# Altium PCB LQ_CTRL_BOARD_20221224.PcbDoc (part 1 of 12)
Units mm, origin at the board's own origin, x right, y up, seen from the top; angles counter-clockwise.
Board outline 260 x 142 mm, 6 copper layers (Top Layer, Mid-Layer 1, Mid-Layer 2, Mid-Layer 3, Mid-Layer 4, Bottom Layer); 1105 components, 1039 nets, 3898 pads, 1277 vias.
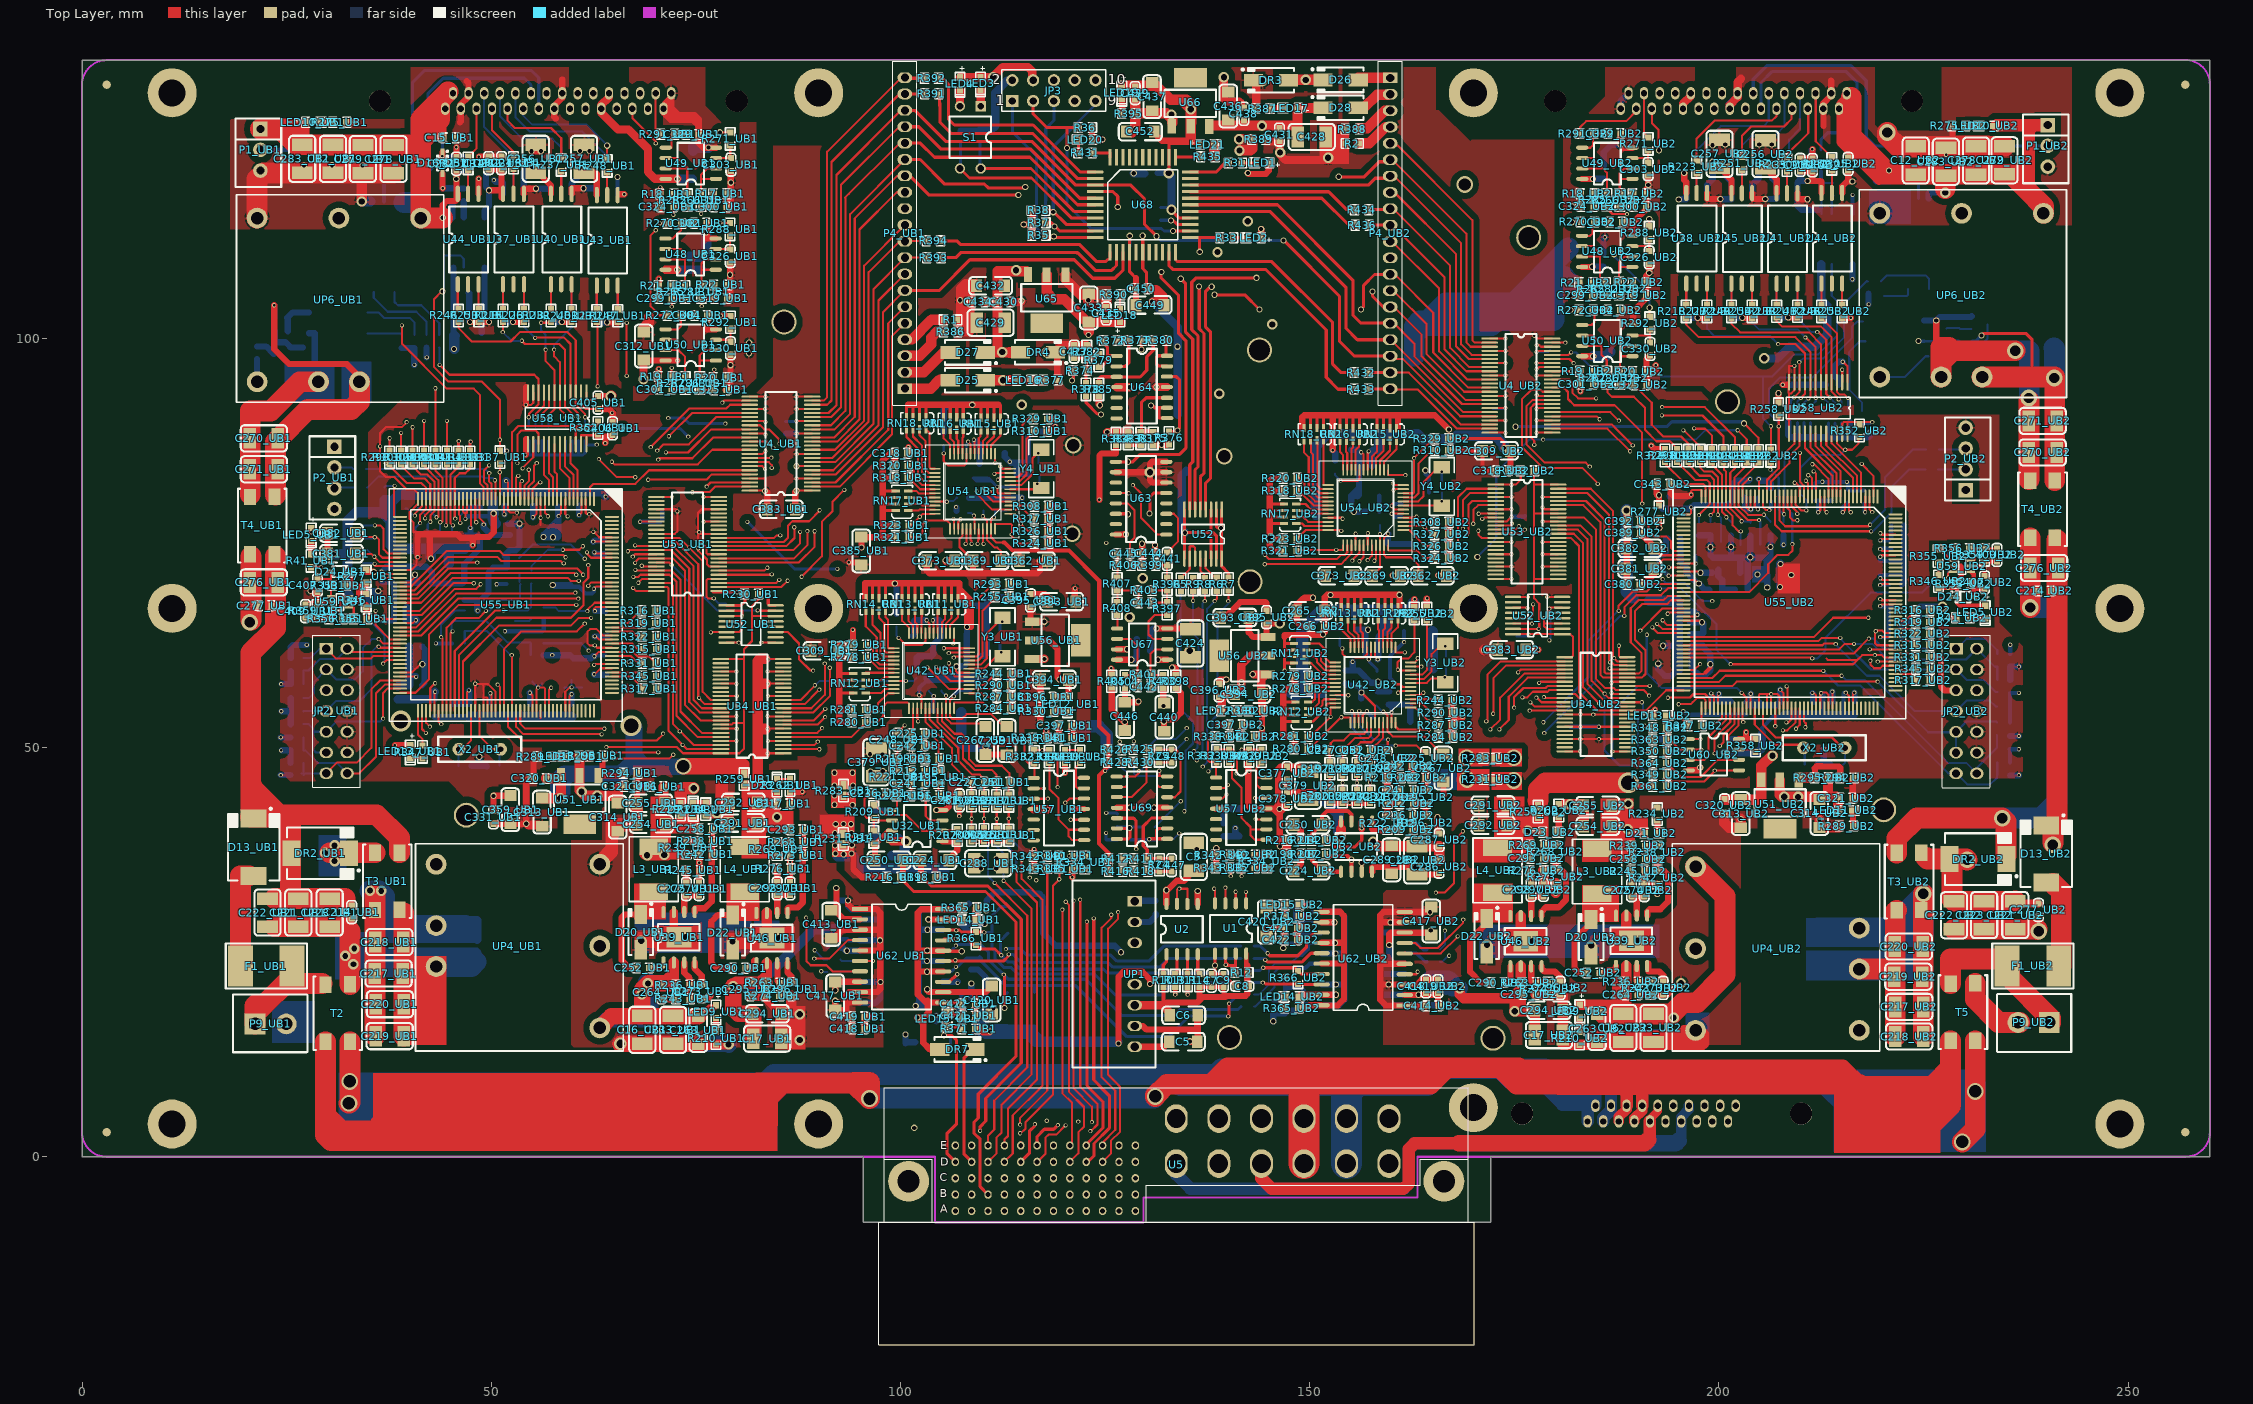
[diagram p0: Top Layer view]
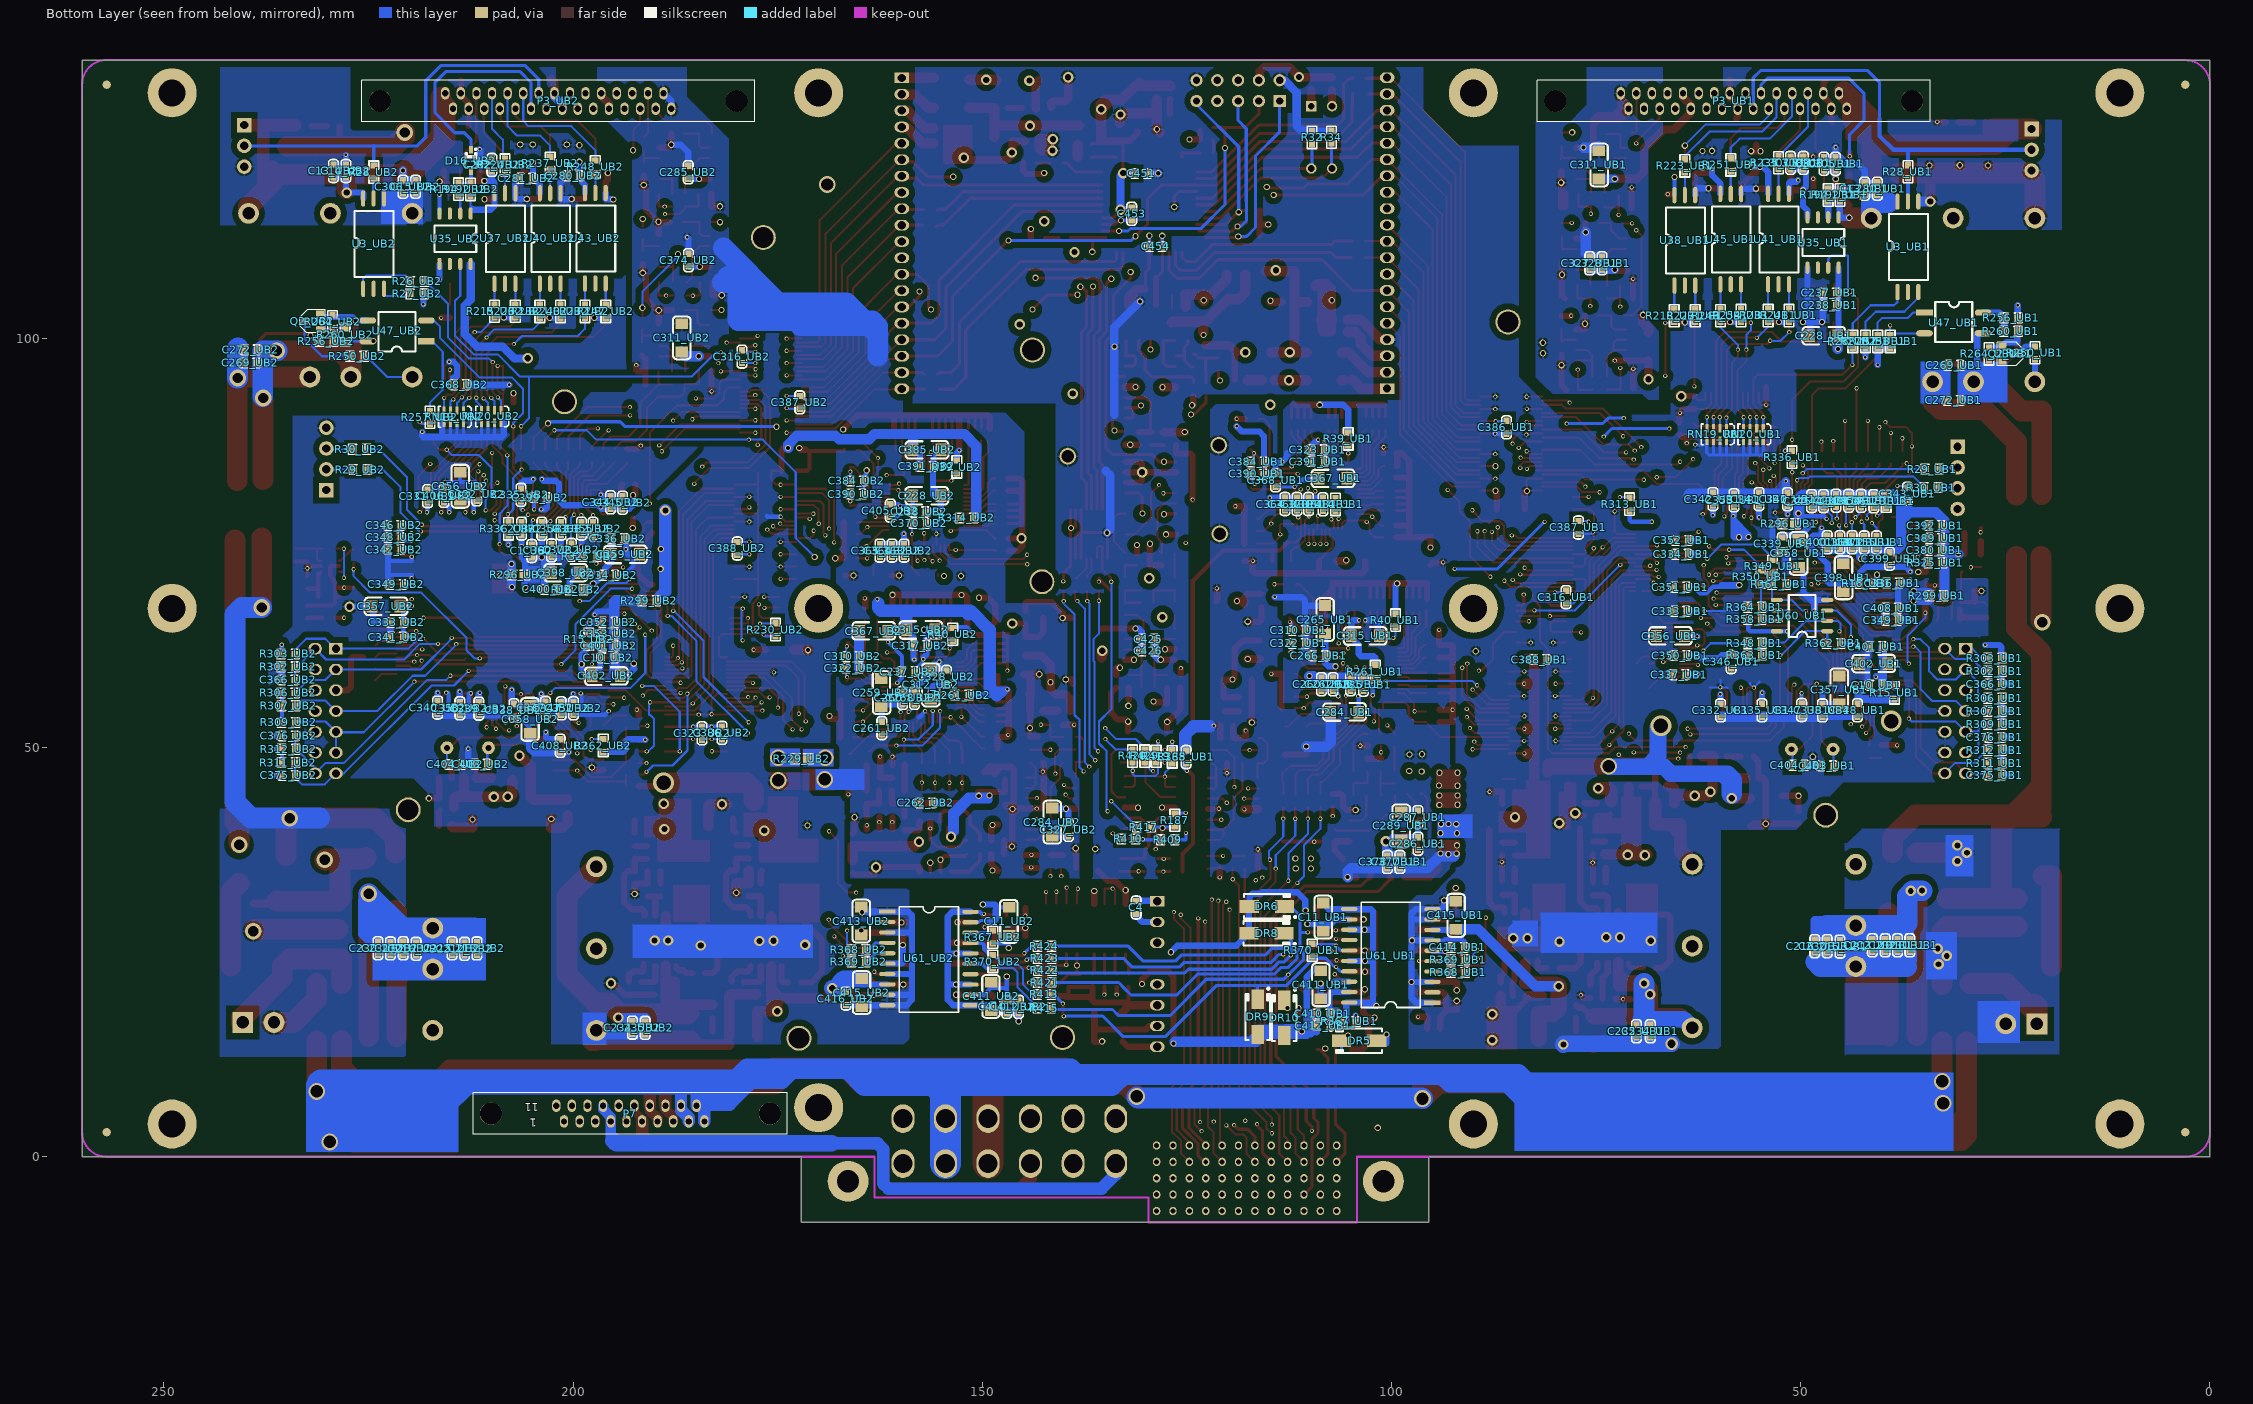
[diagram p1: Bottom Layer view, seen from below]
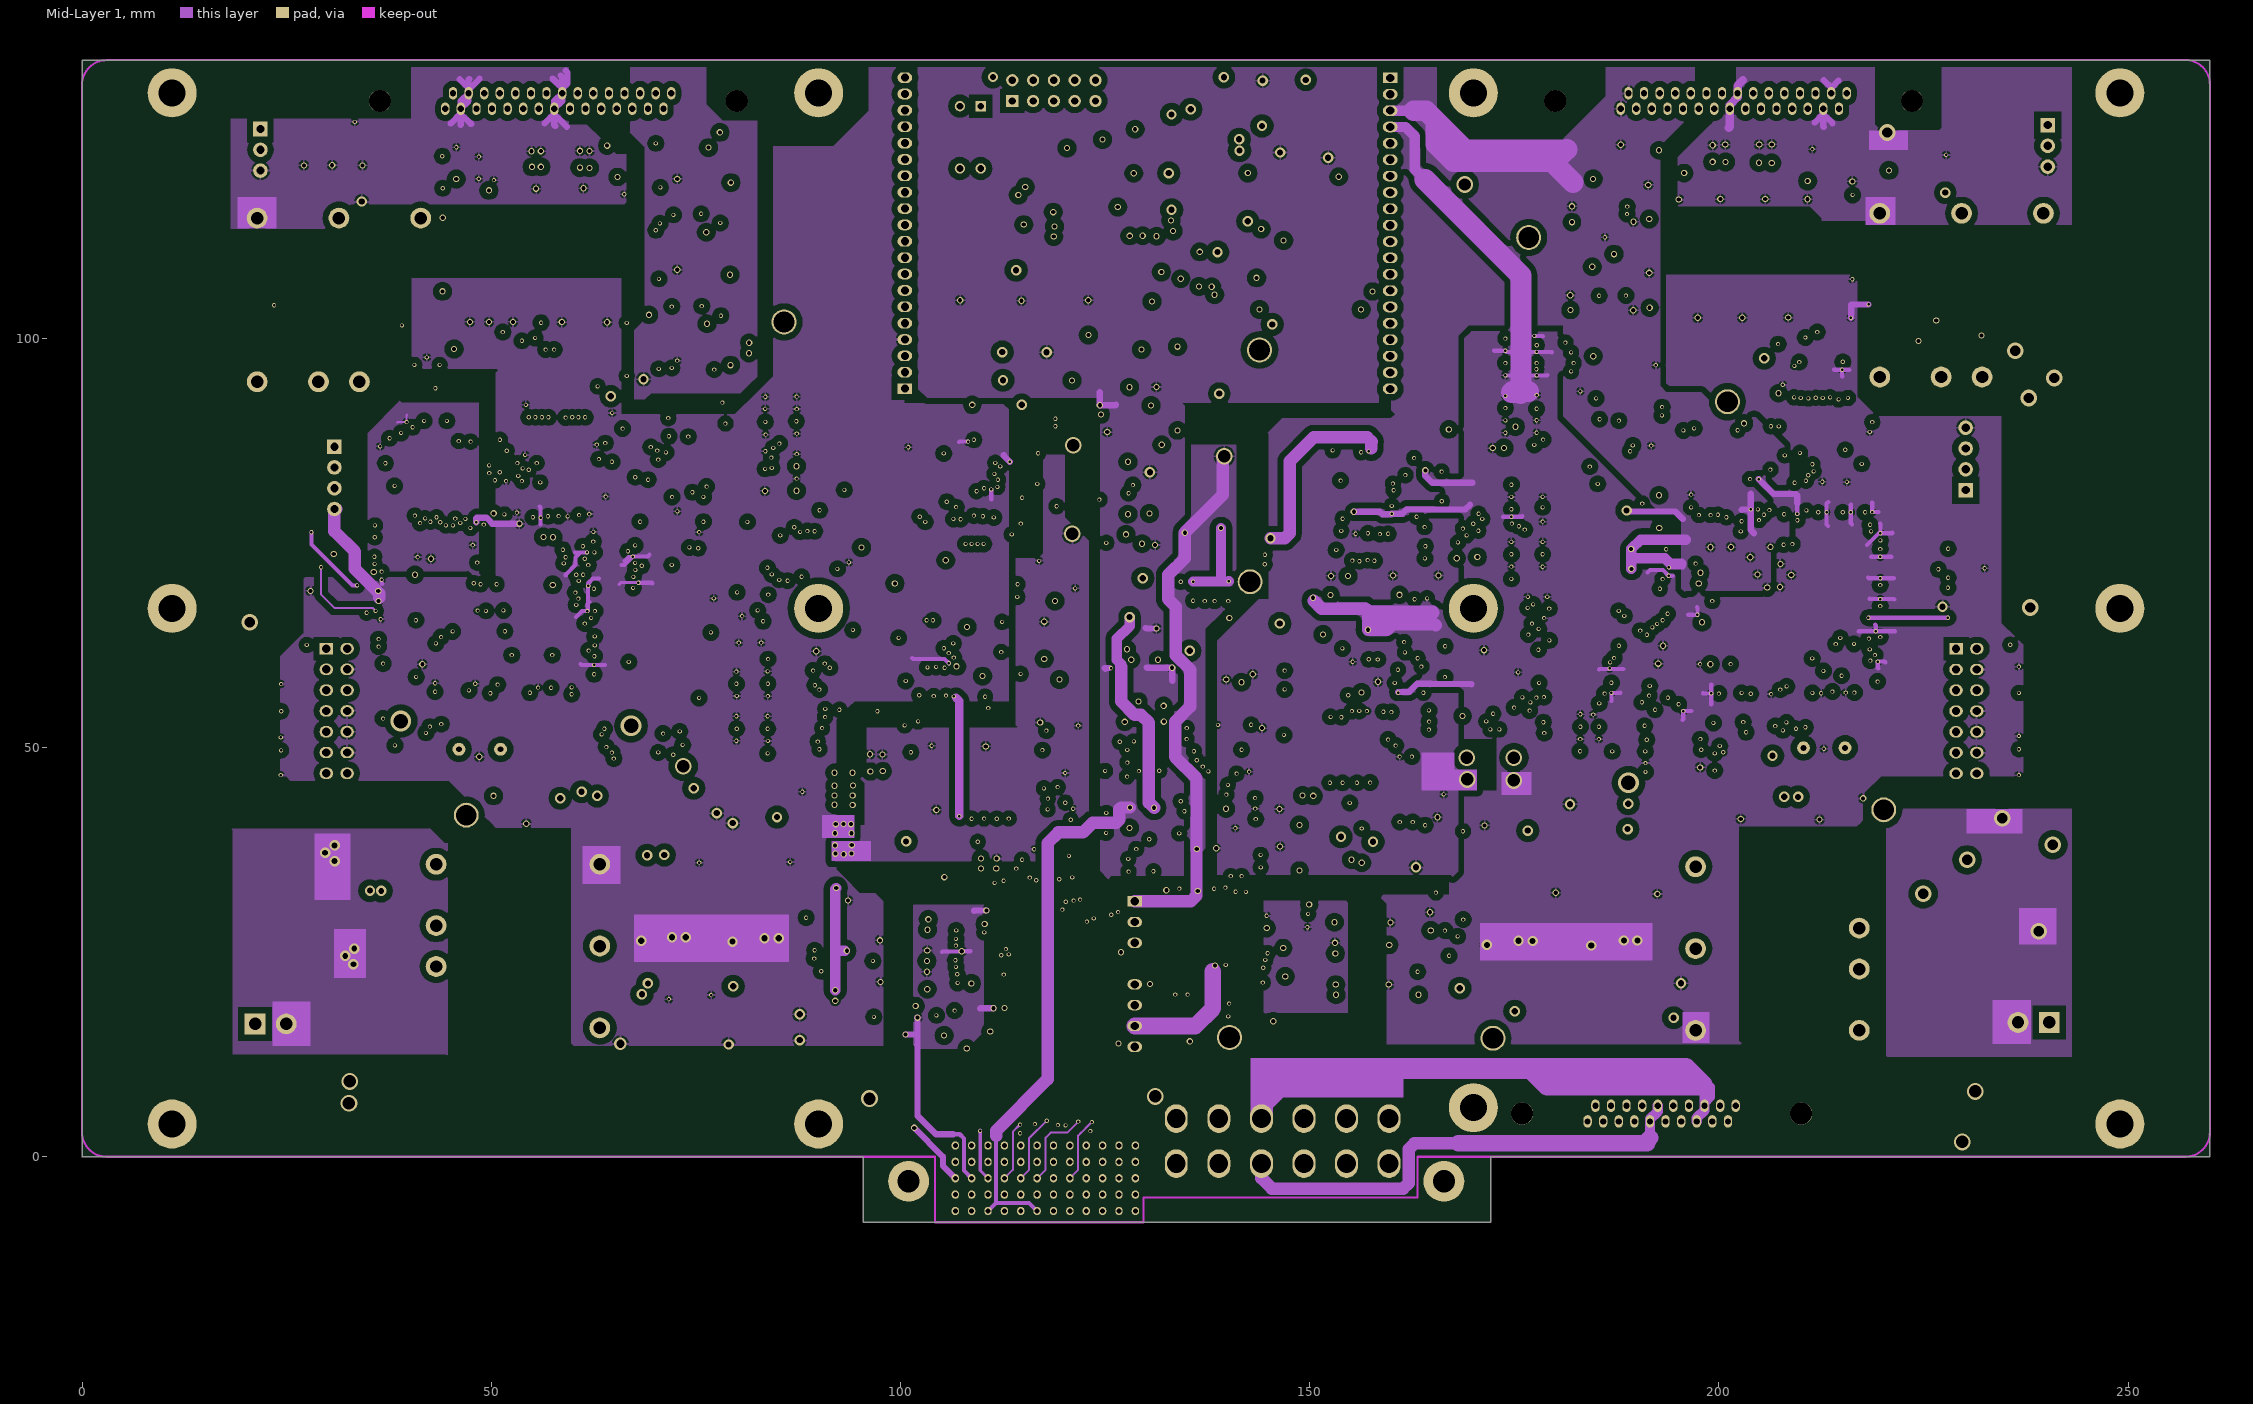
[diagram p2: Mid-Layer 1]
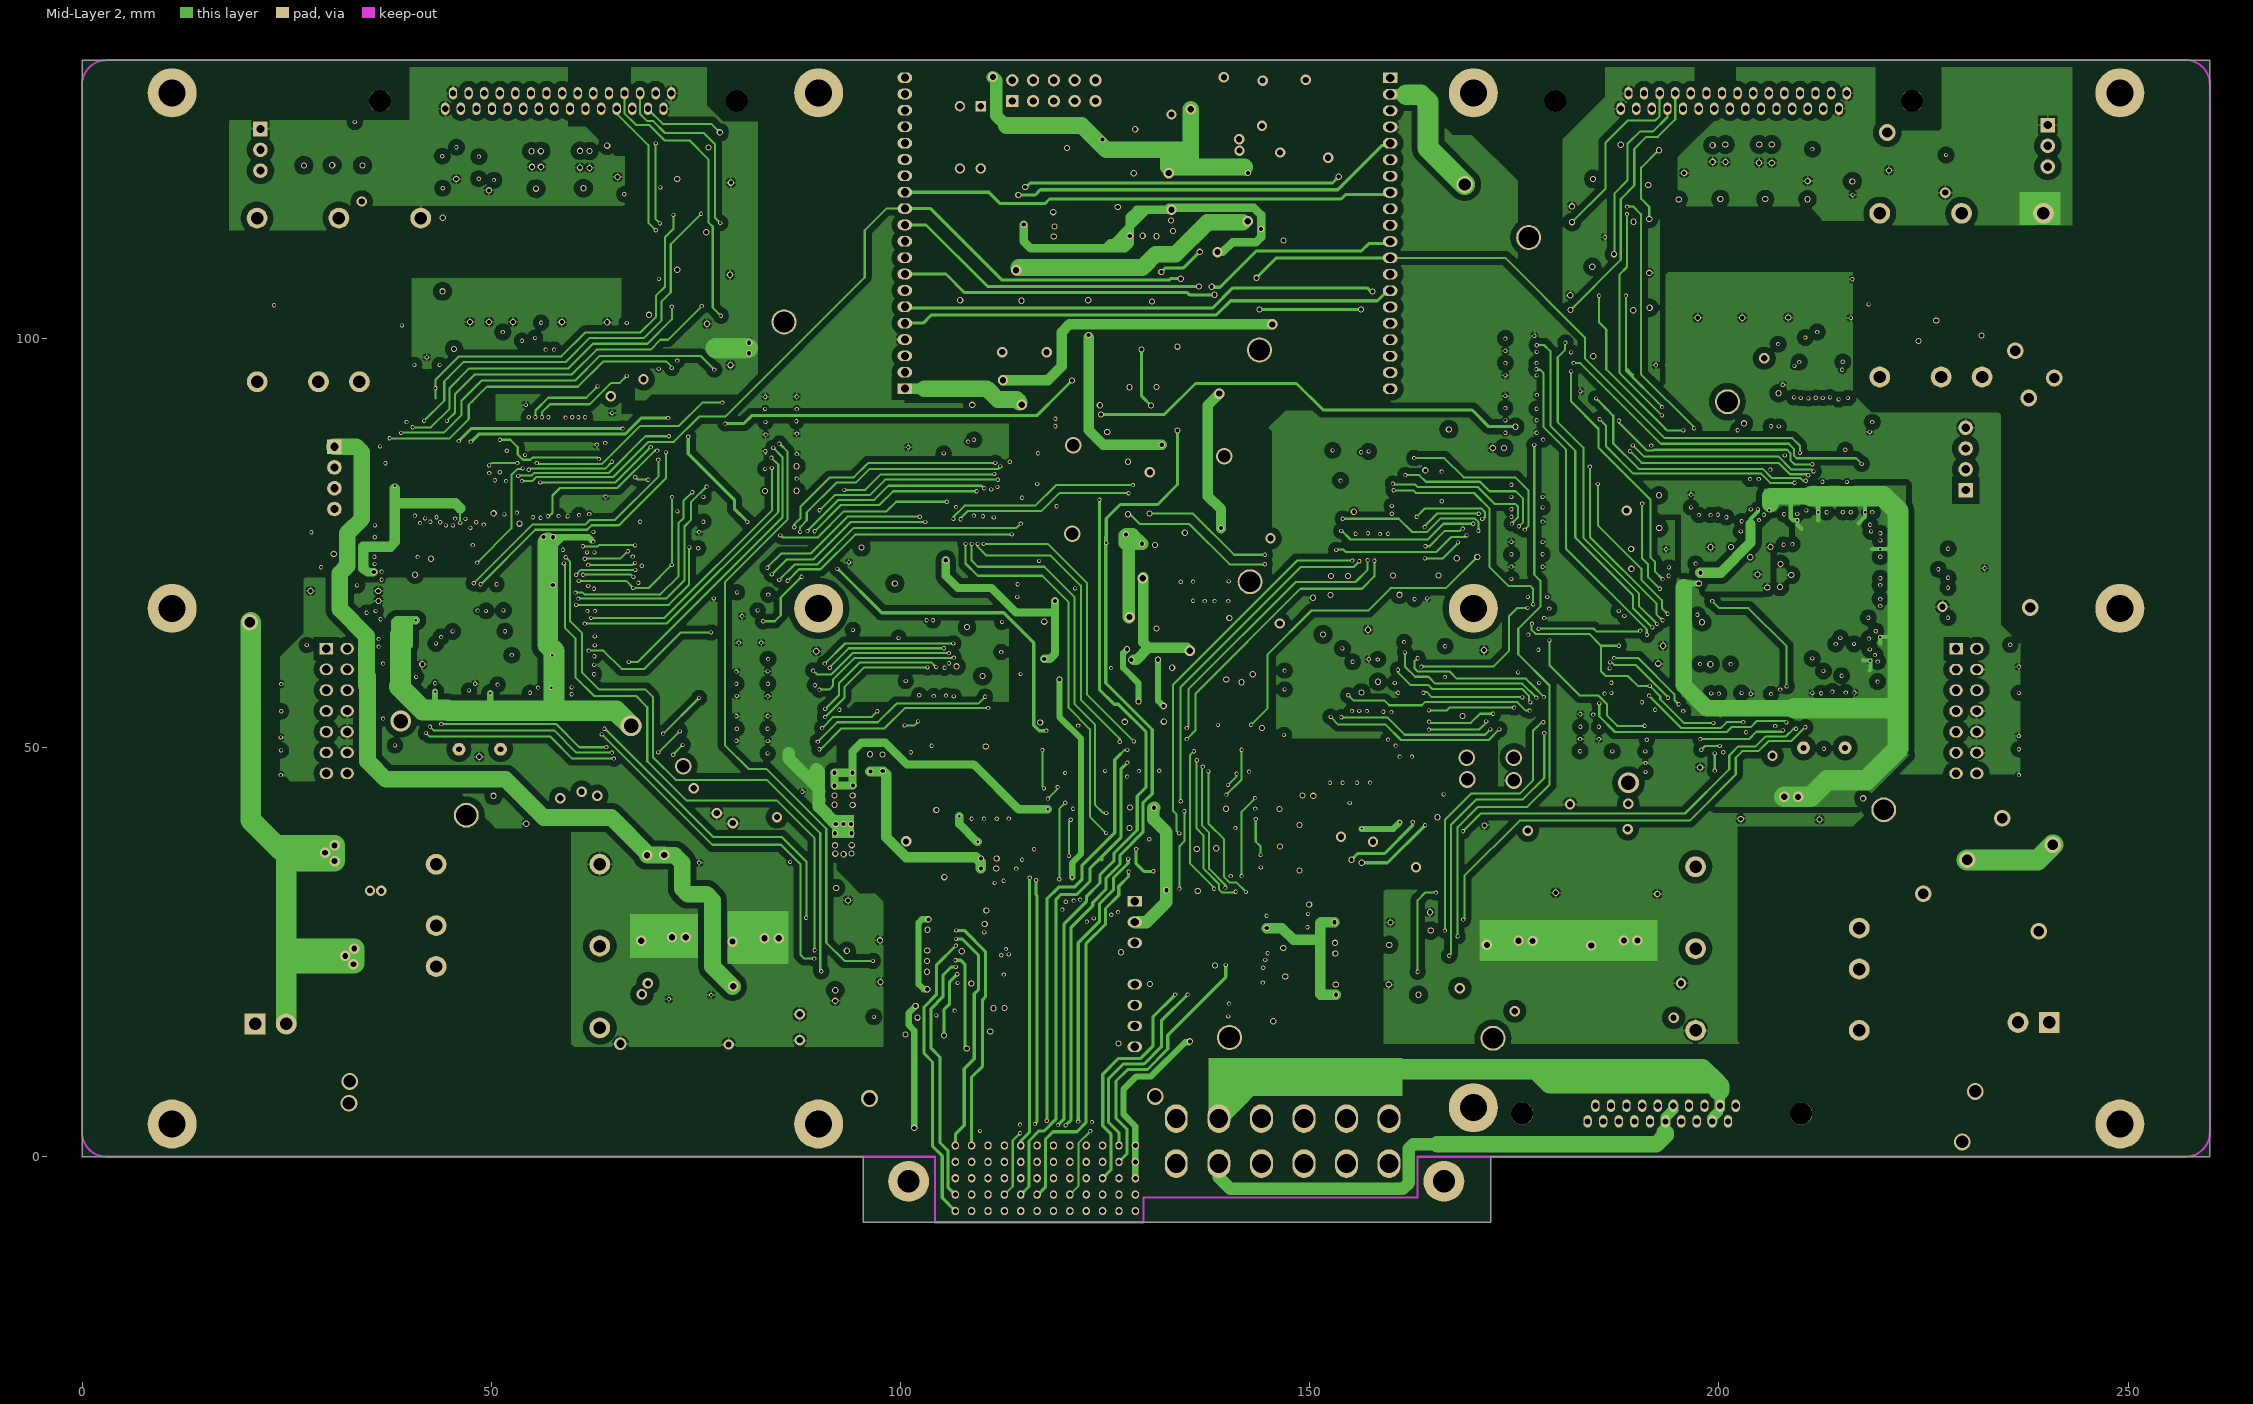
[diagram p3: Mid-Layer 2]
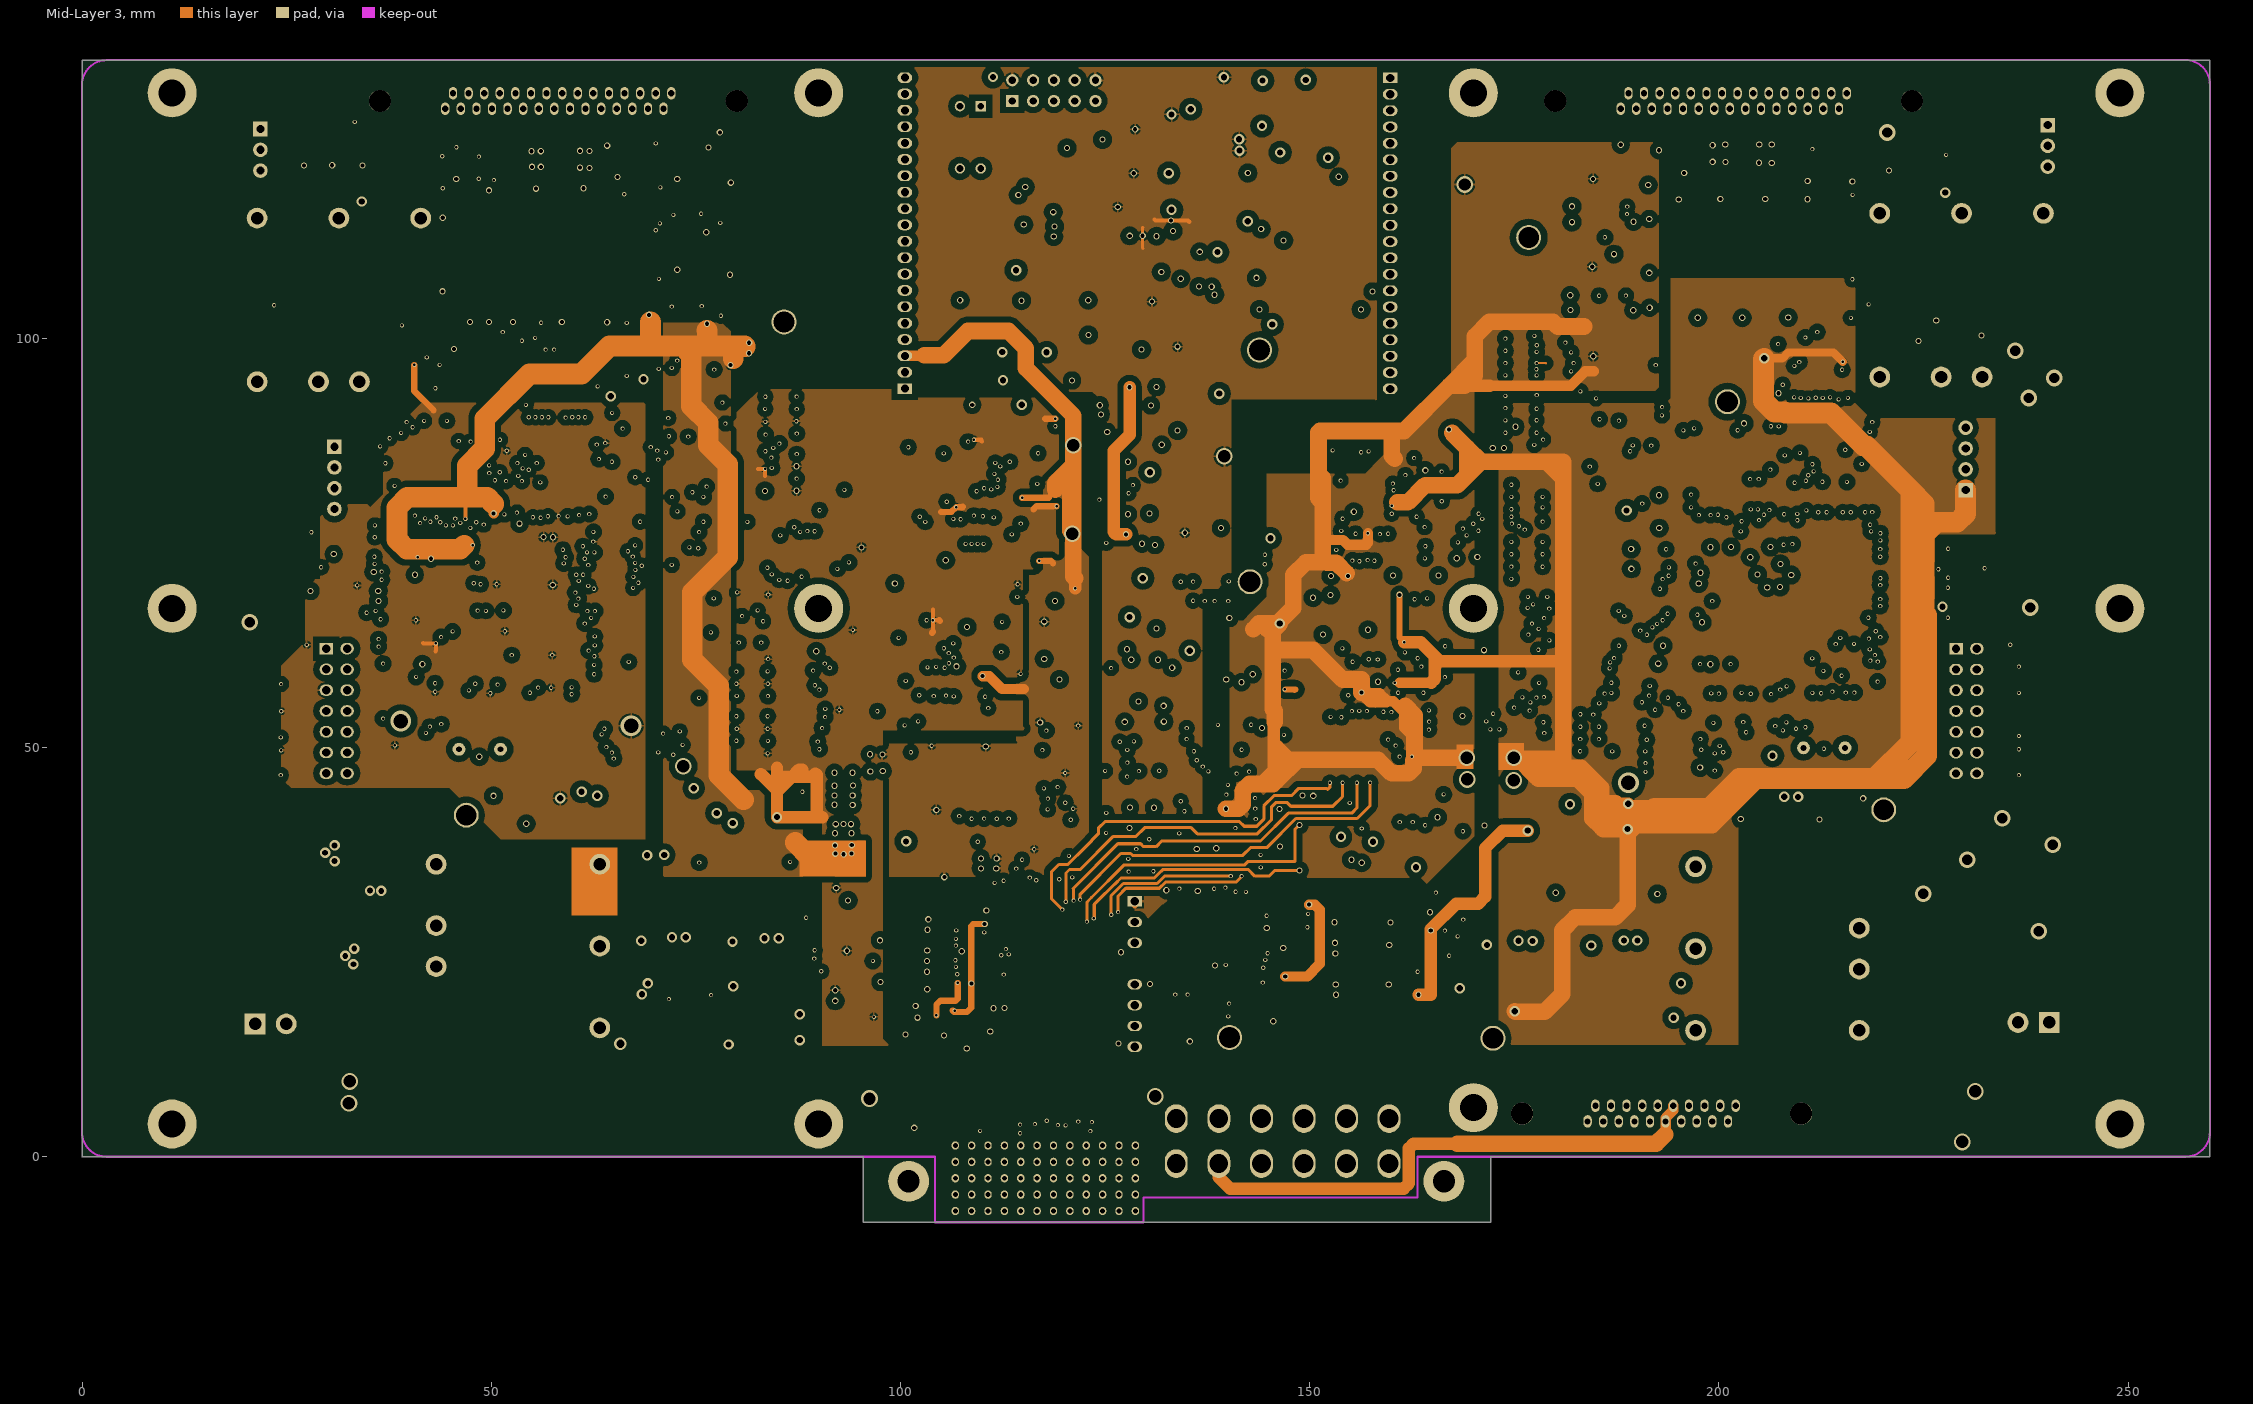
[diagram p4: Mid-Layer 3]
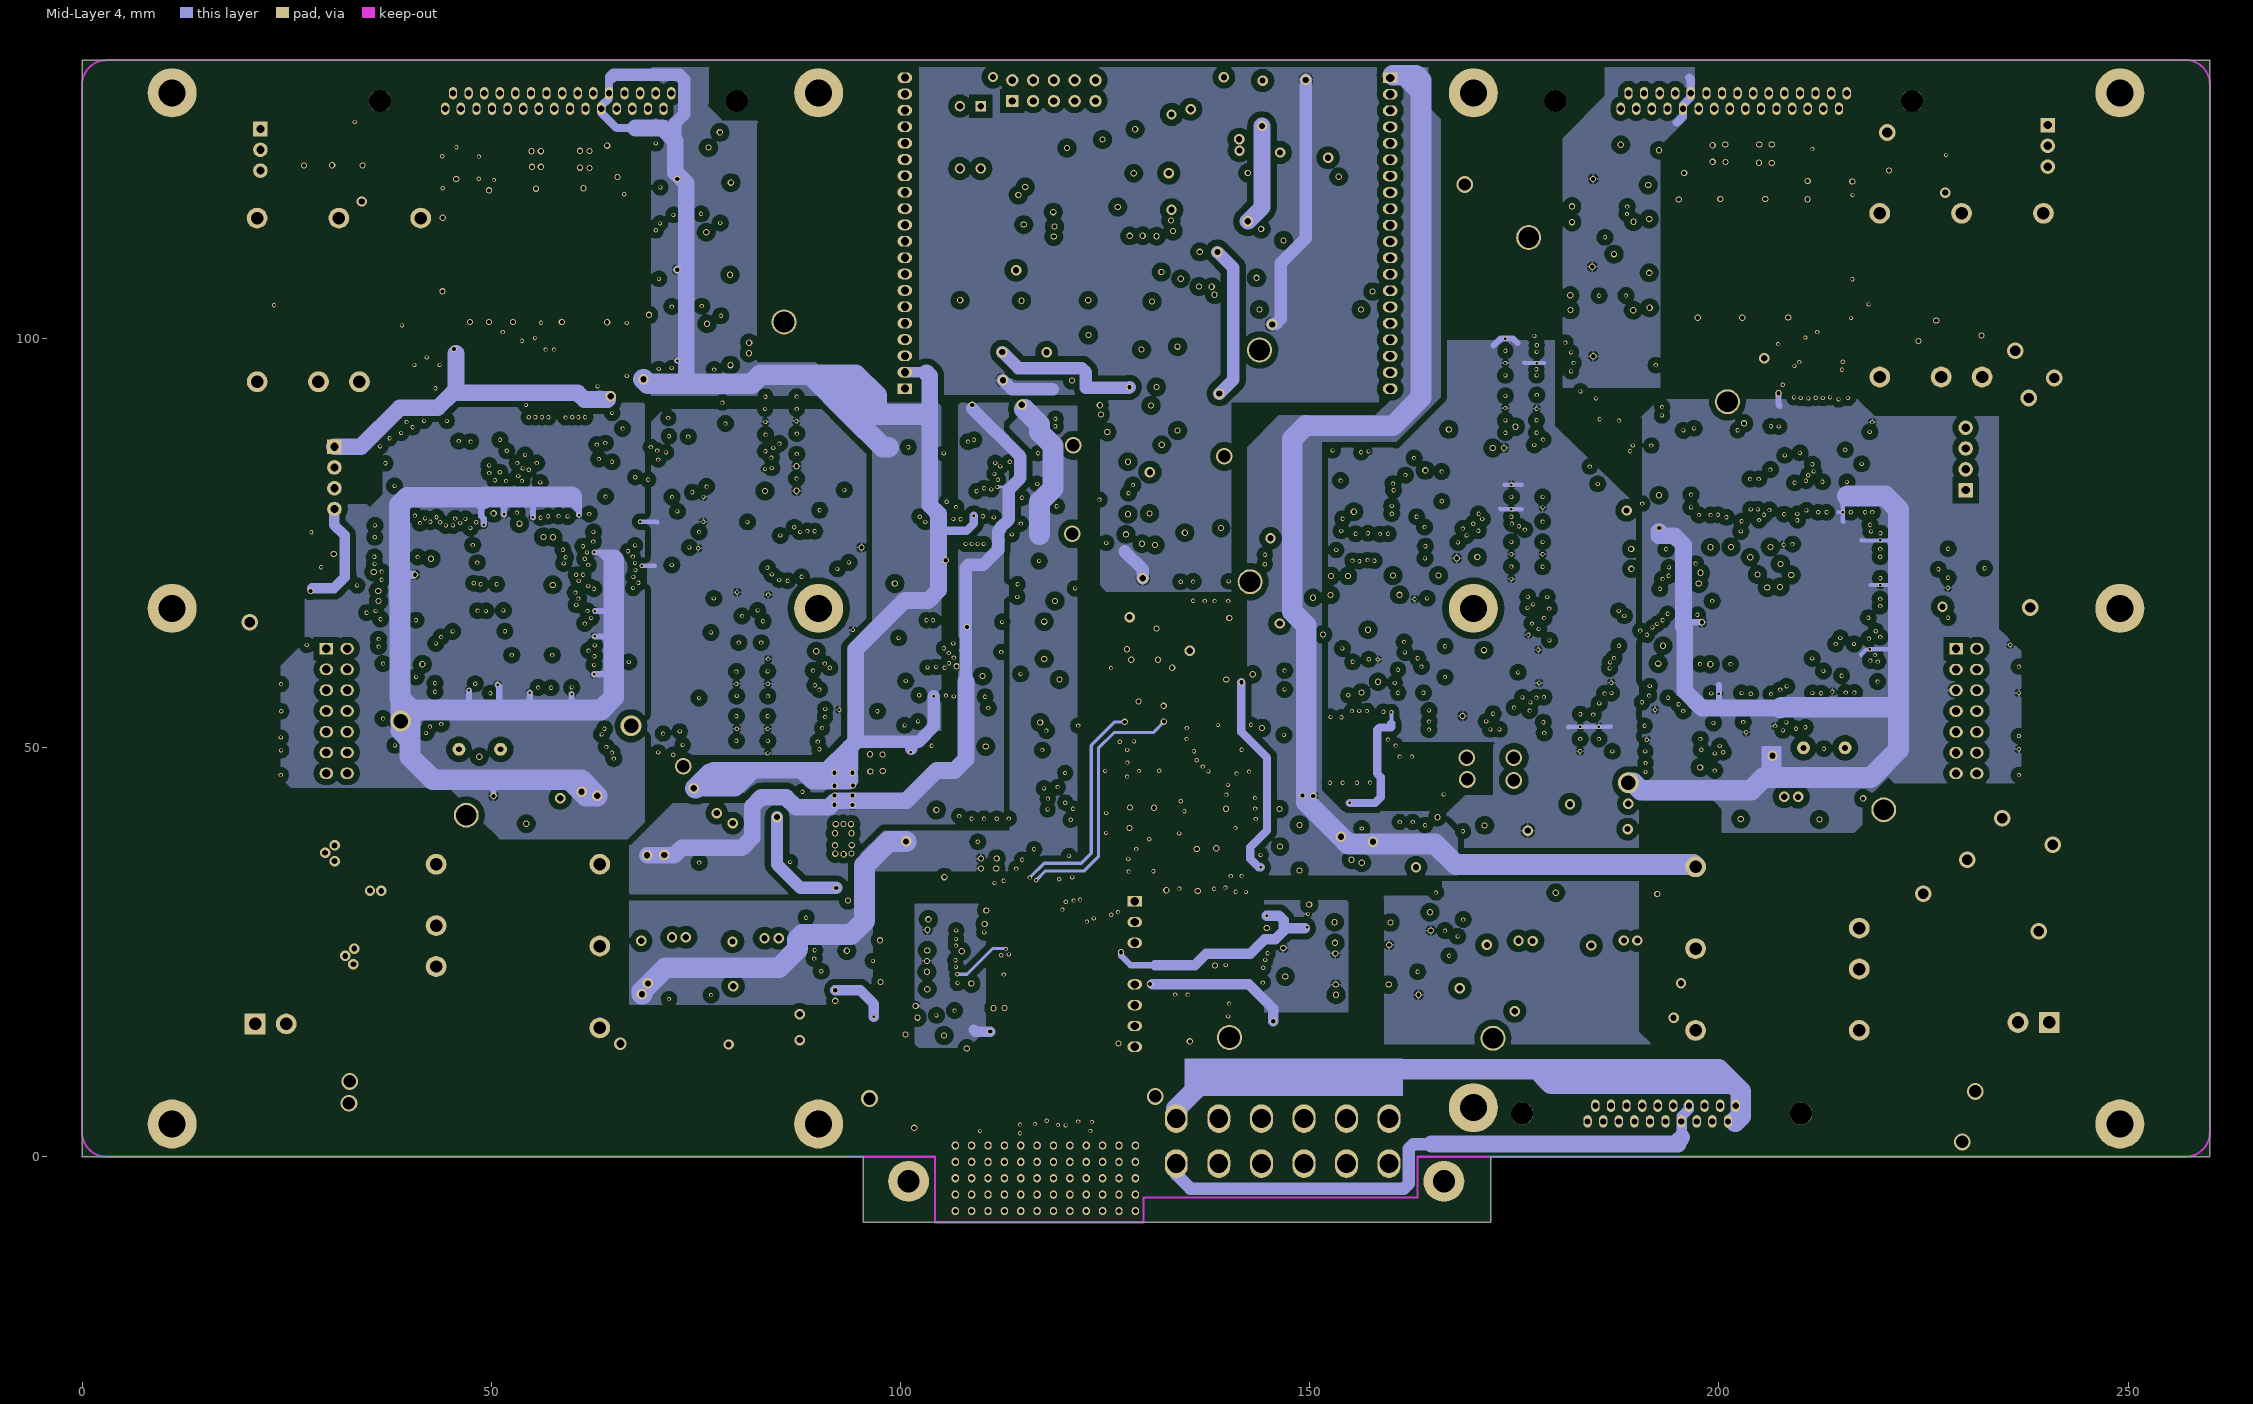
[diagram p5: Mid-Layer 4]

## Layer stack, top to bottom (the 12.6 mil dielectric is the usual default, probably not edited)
Top Layer: signal copper 0.0356
Dielectric: core 0.32, FR-4, Dk 4.8
Mid-Layer 1: signal copper 0.0356
Dielectric: prepreg 0.32, FR-4, Dk 4.8
Mid-Layer 2: signal copper 0.0356
Dielectric: core 0.32, FR-4, Dk 4.8
Mid-Layer 3: signal copper 0.0356
Dielectric: prepreg 0.32, FR-4, Dk 4.8
Mid-Layer 4: signal copper 0.0356
Dielectric: core 0.32, FR-4, Dk 4.8
Bottom Layer: signal copper 0.0356

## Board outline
0,134 0,0 0.025,-0.025 95.479,-0.025 95.479,-8.001 172.11,-8.001 172.11,-0.026 172.137,0 260,0 260,134 0,134

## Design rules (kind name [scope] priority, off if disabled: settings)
Clearance Clearance_1 [InPolygon] p1: gap=0.762
Clearance [All] p2: gap=0.203
HoleSize [All] p1: absolutevalues=TRUE maxlimit=12.7 minlimit=0.025 maxpercent=80.000 minpercent=20.000
MinimumSolderMaskSliver [All] p1: minsoldermaskwidth=0
PolygonConnect [All] p1: connectstyle=Relief reliefconductorwidth=0.254 reliefentries=4 polygonreliefangle="90 Angle" airgapwidth=0.254
RoutingVias [All] p1: holewidth=0.508 width=0.762 viastyle="Through Hole" minholewidth=0.305 minwidth=0.508 maxholewidth=2.032 maxwidth=2.54
SilkToSilkClearance [All] p1: silktosilkclearance=0
SilkToSolderMaskClearance [IsPad] p1: minsilkscreentomaskgap=0 clearancetoexposedcopper=TRUE
SolderMaskExpansion [All] p1: expansion=0.102
Width [All] p1: maxlimit=5.08 minlimit=0.254 preferedwidth=0.254 minimp=50.000000 maximp=50.000000 favimp=50.000000
24 further rules are at their usual default settings.

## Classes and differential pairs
component class UB2: C1_UB2 C2_UB2 C10_UB2 C11_UB2 C12_UB2 C13_UB2 C14_UB2 C15_UB2 C16_UB2 C17_UB2 C212_UB2 C213_UB2 C214_UB2 C215_UB2 C216_UB2 C217_UB2 C218_UB2 C219_UB2 C220_UB2 C221_UB2 C222_UB2 C223_UB2 C224_UB2 C225_UB2 C227_UB2 C228_UB2 C230_UB2 C231_UB2 C232_UB2 C233_UB2 C234_UB2 C235_UB2 C236_UB2 C237_UB2 C238_UB2 C241_UB2 C242_UB2 C248_UB2 C250_UB2 C251_UB2 C252_UB2 C254_UB2 C255_UB2 C256_UB2 C257_UB2 C258_UB2 C259_UB2 C260_UB2 C261_UB2 C262_UB2 C263_UB2 C264_UB2 C265_UB2 C266_UB2 C267_UB2 C268_UB2 C269_UB2 C270_UB2 C271_UB2 C272_UB2 C273_UB2 C274_UB2 C275_UB2 C276_UB2 C277_UB2 C278_UB2 C279_UB2 C280_UB2 C281_UB2 C282_UB2 C283_UB2 C284_UB2 C285_UB2 C286_UB2 C287_UB2 C288_UB2 C289_UB2 C290_UB2 C291_UB2 C292_UB2 C293_UB2 C294_UB2 C295_UB2 C296_UB2 C297_UB2 C298_UB2 C299_UB2 C300_UB2 C301_UB2 C302_UB2 C303_UB2 C304_UB2 C305_UB2 C306_UB2 C307_UB2 C308_UB2 C309_UB2 C310_UB2 C311_UB2 C312_UB2 C313_UB2 C314_UB2 C315_UB2 C316_UB2 C317_UB2 C318_UB2 C319_UB2 C320_UB2 C321_UB2 C322_UB2 C323_UB2 C324_UB2 C325_UB2 C326_UB2 C327_UB2 C328_UB2 C329_UB2 C330_UB2 C331_UB2 C332_UB2 C333_UB2 C334_UB2 C335_UB2 C336_UB2 C337_UB2 C338_UB2 C339_UB2 C340_UB2 C341_UB2 C342_UB2 C343_UB2 C344_UB2 C345_UB2 C346_UB2 C347_UB2 C348_UB2 C349_UB2 C350_UB2 C351_UB2 C352_UB2 C353_UB2 C354_UB2 C355_UB2 C356_UB2 C357_UB2 C358_UB2 C359_UB2 C360_UB2 C361_UB2 C362_UB2 C363_UB2 C364_UB2 C365_UB2 C366_UB2 C367_UB2 C368_UB2 C369_UB2 C370_UB2 C371_UB2 C372_UB2 C373_UB2 C374_UB2 C375_UB2 C376_UB2 C377_UB2 C378_UB2 C379_UB2 C380_UB2 C381_UB2 C382_UB2 C383_UB2 C384_UB2 C385_UB2 C386_UB2 C387_UB2 C388_UB2 C389_UB2 C390_UB2 C391_UB2 C392_UB2 C393_UB2 C394_UB2 C395_UB2 C396_UB2 C397_UB2 C398_UB2 C399_UB2 C400_UB2 C401_UB2 C402_UB2 C403_UB2 C404_UB2 C405_UB2 C406_UB2 C407_UB2 C408_UB2 C409_UB2 C410_UB2 C411_UB2 C412_UB2 C413_UB2 C414_UB2 C415_UB2 C416_UB2 C417_UB2 C418_UB2 C419_UB2 C420_UB2 C421_UB2 C422_UB2 D13_UB2 D16_UB2 D20_UB2 D21_UB2 D22_UB2 D23_UB2 D24_UB2 DR2_UB2 F1_UB2 JP2_UB2 L3_UB2 L4_UB2 LED5_UB2 LED9_UB2 LED10_UB2 LED11_UB2 LED12_UB2 LED13_UB2 LED14_UB2 LED15_UB2 P1_UB2 P2_UB2 P3_UB2 P4_UB2 P9_UB2 Q2_UB2 R3_UB2 R4_UB2 R15_UB2 R16_UB2 R17_UB2 R18_UB2 R19_UB2 R20_UB2 R21_UB2 R22_UB2 R23_UB2 R26_UB2 R27_UB2 R28_UB2 R29_UB2 R30_UB2 R39_UB2 R40_UB2 R41_UB2 R192_UB2 R194_UB2 R195_UB2 R196_UB2 R197_UB2 R198_UB2 R200_UB2 R203_UB2 R205_UB2 R207_UB2 R209_UB2 R210_UB2 R212_UB2 R213_UB2 R214_UB2 R215_UB2 R216_UB2 R217_UB2 R218_UB2 R219_UB2 R220_UB2 R221_UB2 R222_UB2 R223_UB2 R224_UB2 R225_UB2 R226_UB2 R227_UB2 R228_UB2 R229_UB2 R230_UB2 R231_UB2 R232_UB2 R233_UB2 R234_UB2 R235_UB2 R236_UB2 R237_UB2 R238_UB2 R239_UB2 R240_UB2 R241_UB2 R242_UB2 R243_UB2 R244_UB2 R245_UB2 R246_UB2 R247_UB2 R248_UB2 R249_UB2 R250_UB2 R251_UB2 R252_UB2 R253_UB2 R254_UB2 R255_UB2 R256_UB2 R257_UB2 R258_UB2 R259_UB2 R260_UB2 R261_UB2 R262_UB2 R263_UB2 R264_UB2 R265_UB2 R266_UB2 R267_UB2 R268_UB2 R269_UB2 R270_UB2 R271_UB2 R272_UB2 R273_UB2 R274_UB2 R275_UB2 R276_UB2 R277_UB2 R278_UB2 R279_UB2 R280_UB2 R281_UB2 R282_UB2 R283_UB2 R284_UB2 R285_UB2 R286_UB2 R287_UB2 R288_UB2 R289_UB2 R290_UB2 R291_UB2 R292_UB2 R293_UB2 R294_UB2 R295_UB2 R296_UB2 R297_UB2 R298_UB2 R299_UB2 R300_UB2 R301_UB2 R302_UB2 R303_UB2 R304_UB2 R305_UB2 R306_UB2 R307_UB2 R308_UB2 R309_UB2 R310_UB2 R311_UB2 R312_UB2 R313_UB2 R314_UB2 R315_UB2 R316_UB2 R317_UB2 R318_UB2 R319_UB2 R320_UB2 R321_UB2 R322_UB2 R323_UB2 R324_UB2 R325_UB2 R326_UB2 R327_UB2 R328_UB2 R329_UB2 R330_UB2 R331_UB2 R332_UB2 R333_UB2 R334_UB2 R335_UB2 R336_UB2 R337_UB2 R338_UB2 R339_UB2 R340_UB2 R341_UB2 R342_UB2 R343_UB2 R344_UB2 R345_UB2 R346_UB2 R347_UB2 R348_UB2 R349_UB2 R350_UB2 R352_UB2 R353_UB2 R355_UB2 R356_UB2 R358_UB2 R359_UB2 R361_UB2 R362_UB2 R363_UB2 R364_UB2 R365_UB2 R366_UB2 R367_UB2 R368_UB2 R369_UB2 R370_UB2 R371_UB2 RN11_UB2 RN12_UB2 RN13_UB2 RN14_UB2 RN15_UB2 RN16_UB2 RN17_UB2 RN18_UB2 RN19_UB2 RN20_UB2 T3_UB2 T4_UB2 U3_UB2 U4_UB2 U32_UB2 U34_UB2 U35_UB2 U37_UB2 U38_UB2 U39_UB2 U40_UB2 U41_UB2 U42_UB2 U43_UB2 U44_UB2 U45_UB2 U46_UB2 U47_UB2 U48_UB2 U49_UB2 U50_UB2 U51_UB2 U52_UB2 U53_UB2 U54_UB2 U55_UB2 U56_UB2 U57_UB2 U58_UB2 U59_UB2 U60_UB2 U61_UB2 U62_UB2 UP4_UB2 UP6_UB2 X2_UB2 Y3_UB2 Y4_UB2
component class UB1: C1_UB1 C2_UB1 C10_UB1 C11_UB1 C12_UB1 C13_UB1 C14_UB1 C15_UB1 C16_UB1 C17_UB1 C212_UB1 C213_UB1 C214_UB1 C215_UB1 C216_UB1 C217_UB1 C218_UB1 C219_UB1 C220_UB1 C221_UB1 C222_UB1 C223_UB1 C224_UB1 C225_UB1 C227_UB1 C228_UB1 C230_UB1 C231_UB1 C232_UB1 C233_UB1 C234_UB1 C235_UB1 C236_UB1 C237_UB1 C238_UB1 C241_UB1 C242_UB1 C248_UB1 C250_UB1 C251_UB1 C252_UB1 C254_UB1 C255_UB1 C256_UB1 C257_UB1 C258_UB1 C259_UB1 C260_UB1 C261_UB1 C262_UB1 C263_UB1 C264_UB1 C265_UB1 C266_UB1 C267_UB1 C268_UB1 C269_UB1 C270_UB1 C271_UB1 C272_UB1 C273_UB1 C274_UB1 C275_UB1 C276_UB1 C277_UB1 C278_UB1 C279_UB1 C280_UB1 C281_UB1 C282_UB1 C283_UB1 C284_UB1 C285_UB1 C286_UB1 C287_UB1 C288_UB1 C289_UB1 C290_UB1 C291_UB1 C292_UB1 C293_UB1 C294_UB1 C295_UB1 C296_UB1 C297_UB1 C298_UB1 C299_UB1 C300_UB1 C301_UB1 C302_UB1 C303_UB1 C304_UB1 C305_UB1 C306_UB1 C307_UB1 C308_UB1 C309_UB1 C310_UB1 C311_UB1 C312_UB1 C313_UB1 C314_UB1 C315_UB1 C316_UB1 C317_UB1 C318_UB1 C319_UB1 C320_UB1 C321_UB1 C322_UB1 C323_UB1 C324_UB1 C325_UB1 C326_UB1 C327_UB1 C328_UB1 C329_UB1 C330_UB1 C331_UB1 C332_UB1 C333_UB1 C334_UB1 C335_UB1 C336_UB1 C337_UB1 C338_UB1 C339_UB1 C340_UB1 C341_UB1 C342_UB1 C343_UB1 C344_UB1 C345_UB1 C346_UB1 C347_UB1 C348_UB1 C349_UB1 C350_UB1 C351_UB1 C352_UB1 C353_UB1 C354_UB1 C355_UB1 C356_UB1 C357_UB1 C358_UB1 C359_UB1 C360_UB1 C361_UB1 C362_UB1 C363_UB1 C364_UB1 C365_UB1 C366_UB1 C367_UB1 C368_UB1 C369_UB1 C370_UB1 C371_UB1 C372_UB1 C373_UB1 C374_UB1 C375_UB1 C376_UB1 C377_UB1 C378_UB1 C379_UB1 C380_UB1 C381_UB1 C382_UB1 C383_UB1 C384_UB1 C385_UB1 C386_UB1 C387_UB1 C388_UB1 C389_UB1 C390_UB1 C391_UB1 C392_UB1 C393_UB1 C394_UB1 C395_UB1 C396_UB1 C397_UB1 C398_UB1 C399_UB1 C400_UB1 C401_UB1 C402_UB1 C403_UB1 C404_UB1 C405_UB1 C406_UB1 C407_UB1 C408_UB1 C409_UB1 C410_UB1 C411_UB1 C412_UB1 C413_UB1 C414_UB1 C415_UB1 C416_UB1 C417_UB1 C418_UB1 C419_UB1 C420_UB1 C421_UB1 C422_UB1 D13_UB1 D16_UB1 D20_UB1 D21_UB1 D22_UB1 D23_UB1 D24_UB1 DR2_UB1 F1_UB1 JP2_UB1 L3_UB1 L4_UB1 LED5_UB1 LED9_UB1 LED10_UB1 LED11_UB1 LED12_UB1 LED13_UB1 LED14_UB1 LED15_UB1 P1_UB1 P2_UB1 P3_UB1 P4_UB1 P9_UB1 Q2_UB1 R3_UB1 R4_UB1 R15_UB1 R16_UB1 R17_UB1 R18_UB1 R19_UB1 R20_UB1 R21_UB1 R22_UB1 R23_UB1 R26_UB1 R27_UB1 R28_UB1 R29_UB1 R30_UB1 R39_UB1 R40_UB1 R41_UB1 R192_UB1 R194_UB1 R195_UB1 R196_UB1 R197_UB1 R198_UB1 R200_UB1 R203_UB1 R205_UB1 R207_UB1 R209_UB1 R210_UB1 R212_UB1 R213_UB1 R214_UB1 R215_UB1 R216_UB1 R217_UB1 R218_UB1 R219_UB1 R220_UB1 R221_UB1 R222_UB1 R223_UB1 R224_UB1 R225_UB1 R226_UB1 R227_UB1 R228_UB1 R229_UB1 R230_UB1 R231_UB1 R232_UB1 R233_UB1 R234_UB1 R235_UB1 R236_UB1 R237_UB1 R238_UB1 R239_UB1 R240_UB1 R241_UB1 R242_UB1 R243_UB1 R244_UB1 R245_UB1 R246_UB1 R247_UB1 R248_UB1 R249_UB1 R250_UB1 R251_UB1 R252_UB1 R253_UB1 R254_UB1 R255_UB1 R256_UB1 R257_UB1 R258_UB1 R259_UB1 R260_UB1 R261_UB1 R262_UB1 R263_UB1 R264_UB1 R265_UB1 R266_UB1 R267_UB1 R268_UB1 R269_UB1 R270_UB1 R271_UB1 R272_UB1 R273_UB1 R274_UB1 R275_UB1 R276_UB1 R277_UB1 R278_UB1 R279_UB1 R280_UB1 R281_UB1 R282_UB1 R283_UB1 R284_UB1 R285_UB1 R286_UB1 R287_UB1 R288_UB1 R289_UB1 R290_UB1 R291_UB1 R292_UB1 R293_UB1 R294_UB1 R295_UB1 R296_UB1 R297_UB1 R298_UB1 R299_UB1 R300_UB1 R301_UB1 R302_UB1 R303_UB1 R304_UB1 R305_UB1 R306_UB1 R307_UB1 R308_UB1 R309_UB1 R310_UB1 R311_UB1 R312_UB1 R313_UB1 R314_UB1 R315_UB1 R316_UB1 R317_UB1 R318_UB1 R319_UB1 R320_UB1 R321_UB1 R322_UB1 R323_UB1 R324_UB1 R325_UB1 R326_UB1 R327_UB1 R328_UB1 R329_UB1 R330_UB1 R331_UB1 R332_UB1 R333_UB1 R334_UB1 R335_UB1 R336_UB1 R337_UB1 R338_UB1 R339_UB1 R340_UB1 R341_UB1 R342_UB1 R343_UB1 R344_UB1 R345_UB1 R346_UB1 R347_UB1 R348_UB1 R349_UB1 R350_UB1 R352_UB1 R353_UB1 R355_UB1 R356_UB1 R358_UB1 R359_UB1 R361_UB1 R362_UB1 R363_UB1 R364_UB1 R365_UB1 R366_UB1 R367_UB1 R368_UB1 R369_UB1 R370_UB1 R371_UB1 RN11_UB1 RN12_UB1 RN13_UB1 RN14_UB1 RN15_UB1 RN16_UB1 RN17_UB1 RN18_UB1 RN19_UB1 RN20_UB1 T3_UB1 T4_UB1 U3_UB1 U4_UB1 U32_UB1 U34_UB1 U35_UB1 U37_UB1 U38_UB1 U39_UB1 U40_UB1 U41_UB1 U42_UB1 U43_UB1 U44_UB1 U45_UB1 U46_UB1 U47_UB1 U48_UB1 U49_UB1 U50_UB1 U51_UB1 U52_UB1 U53_UB1 U54_UB1 U55_UB1 U56_UB1 U57_UB1 U58_UB1 U59_UB1 U60_UB1 U61_UB1 U62_UB1 UP4_UB1 UP6_UB1 X2_UB1 Y3_UB1 Y4_UB1
component class UB3: C3 C4 C5 C6 C7 C8 C9 C424 C425 C426 C427 C428 C429 C430 C431 C432 C433 C434 C435 C436 C437 C438 C439 C440 C441 C442 C443 C444 C445 C446 C447 C448 C449 C450 C451 C452 C453 C454 D25 D26 D27 D28 DR3 DR4 DR5 DR6 DR7 DR8 DR9 DR10 JP3 LED1 LED2 LED3 LED4 LED16 LED17 LED18 LED19 LED20 LED21 P7 R1 R2 R5 R6 R7 R8 R9 R10 R11 R12 R13 R14 R24 R25 R31 R32 R33 R34 R35 R36 R37 R38 R187 R188 R372 R373 R374 R375 R376 R377 R378 R379 R380 R381 R382 R383 R384 R385 R386 R387 R388 R389 R390 R391 R392 R393 R394 R395 R396 R397 R398 R399 R400 R401 R403 R404 R405 R406 R407 R408 R409 R410 R411 R412 R413 R415 R416 R417 R418 R419 R420 R421 R422 R423 R424 R425 R426 R428 R429 R430 R431 R432 R433 R434 R435 R436 S1 T2 T5 U1 U2 U5 U52 U63 U64 U65 U66 U67 U68 U69 UP1
channel class Ctrl_Board: UB1 UB2

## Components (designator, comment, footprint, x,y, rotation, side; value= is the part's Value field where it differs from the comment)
C1_UB1 "1nF/50V" WP_0603C 45.212,74.295 r90 bottom (schematic designator C1)
C1_UB2 "1nF/50V" WP_0603C 205.054,73.228 r90 bottom (schematic designator C1)
C2_UB1 "1nF/50V" WP_0603C 45.695,80.95 r270 bottom (schematic designator C2)
C2_UB2 "1nF/50V" WP_0603C 206.299,75.971 r90 bottom (schematic designator C2)
C3 "47uF/50V" WP_1210CC 135.839,34.925 r90 top
C4 "0.1uF/50V" WP_0603C 131.191,29.667 r90 bottom
C5 "10uF/25V" WP_1206CC 136.271,14.046 r180 top
C6 "22uF/50V" WP_1206CC 132.893,17.297 r0 top
C7 "0.1uF/50V" WP_0603C 137.998,22.301 r270 top
C8 "0.1uF/50V" WP_0603C 140.97,20.828 r0 top
C9 "0.1uF/50V" WP_0603C 139.471,22.327 r270 top
C10_UB1 "1uF/50V" WP_0603C 39.98,57.607 r0 bottom (schematic designator C401)
C10_UB2 "1uF/50V" WP_0603C 196.494,60.96 r180 bottom (schematic designator C232)
C11_UB1 "22uF/25V" WP_1206CC 108.356,27.559 r90 bottom (schematic designator C11)
C11_UB2 "22uF/25V" WP_1206CC 146.736,30.48 r270 bottom (schematic designator C11)
C12_UB1 "47uF/50V" WP_1210CC 30.652,123.647 r270 top (schematic designator C12)
C12_UB2 "47uF/50V" WP_1210CC 224.053,120.015 r90 top (schematic designator C12)
C13_UB1 "0.1uF/50V" WP_0603C 42.189,119.075 r270 bottom (schematic designator C13)
C13_UB2 "0.1uF/50V" WP_0603C 229.286,121.234 r270 bottom (schematic designator C13)
C14_UB1 "0.1uF/50V" WP_0603C 49.682,122.199 r270 top (schematic designator C14)
C14_UB2 "0.1uF/50V" WP_0603C 227.762,121.234 r270 bottom (schematic designator C14)
C15_UB1 "0.1uF/50V" WP_0603C 45.72,124.511 r180 top (schematic designator C15)
C15_UB2 "0.1uF/50V" WP_0603C 219.253,117.729 r90 bottom (schematic designator C15)
C16_UB1 "47uF/50V" WP_1210CC 68.453,17.221 r270 top (schematic designator C16)
C16_UB2 "47uF/50V" WP_1210CC 188.316,17.45 r270 top (schematic designator C16)
C17_UB1 "47uF/50V" WP_1210CC 81.991,14.427 r0 top (schematic designator C17)
C17_UB2 "47uF/50V" WP_1210CC 177.521,14.859 r0 top (schematic designator C17)
C212_UB1 "0.1uF/50V" WP_0603C 39.675,25.044 r90 bottom (schematic designator C212)
C212_UB2 "0.1uF/50V" WP_0603C 213.258,26.187 r270 bottom (schematic designator C212)
C213_UB1 "0.1uF/50V" WP_0603C 41.25,25.044 r90 bottom (schematic designator C213)
C213_UB2 "0.1uF/50V" WP_0603C 211.76,26.238 r270 bottom (schematic designator C213)
C214_UB1 "0.1uF/50V" WP_0603C 32.944,30.683 r270 top (schematic designator C214)
C214_UB2 "0.1uF/50V" WP_0603C 240.589,69.139 r180 top (schematic designator C214)
C215_UB1 "0.1uF/50V" WP_0603C 45.212,24.892 r90 bottom (schematic designator C215)
C215_UB2 "0.1uF/50V" WP_0603C 214.782,26.264 r270 bottom (schematic designator C215)
C216_UB1 "0.1uF/50V" WP_0603C 48.285,24.943 r90 bottom (schematic designator C216)
C216_UB2 "0.1uF/50V" WP_0603C 219.177,26.187 r270 bottom (schematic designator C216)
C217_UB1 "47uF/50V" WP_1210CC 39.172,22.377 r180 top (schematic designator C217)
C217_UB2 "47uF/50V" WP_1210CC 224.968,18.313 r180 top (schematic designator C217)
C218_UB1 "47uF/50V" WP_1210CC 39.248,26.238 r180 top (schematic designator C218)
C218_UB2 "47uF/50V" WP_1210CC 224.968,14.681 r180 top (schematic designator C218)
C219_UB1 "47uF/50V" WP_1210CC 39.299,14.732 r180 top (schematic designator C219)
C219_UB2 "47uF/50V" WP_1210CC 224.866,21.996 r180 top (schematic designator C219)
C220_UB1 "47uF/50V" WP_1210CC 39.325,18.644 r180 top (schematic designator C220)
C220_UB2 "47uF/50V" WP_1210CC 224.917,25.679 r180 top (schematic designator C220)
C221_UB1 "47uF/50V" WP_1210CC 26.416,31.547 r270 top (schematic designator C221)
C221_UB2 "47uF/50V" WP_1210CC 236.22,31.242 r270 top (schematic designator C221)
C222_UB1 "47uF/50V" WP_1210CC 22.657,31.547 r270 top (schematic designator C222)
C222_UB2 "47uF/50V" WP_1210CC 228.727,31.217 r270 top (schematic designator C222)
C223_UB1 "47uF/50V" WP_1210CC 30.251,31.547 r270 top (schematic designator C223)
C223_UB2 "47uF/50V" WP_1210CC 232.41,31.242 r270 top (schematic designator C223)
C224_UB1 "22uF/25V" WP_1206CC 102.504,36.246 r0 top (schematic designator C224)
C224_UB2 "22uF/25V" WP_1206CC 148.107,34.95 r0 top (schematic designator C224)
C225_UB1 "0.01uF/50V" WP_0603C 102.895,51.689 r180 top (schematic designator C225)
C225_UB2 "0.01uF/50V" WP_0603C 164.16,47.879 r90 top (schematic designator C225)
C227_UB1 "1nF/50V" WP_0603C 110.236,45.771 r180 top (schematic designator C227)
C227_UB2 "1nF/50V" WP_0603C 154.026,49.649 r180 top (schematic designator C227)
C228_UB1 "22uF/25V" WP_1206CC 45.466,100.305 r0 bottom (schematic designator C228)
C228_UB2 "22uF/25V" WP_1206CC 158.496,80.772 r180 bottom (schematic designator C228)
C230_UB1 "0.1uF/50V" WP_0603C 46.761,26.518 r270 bottom (schematic designator C230)
C230_UB2 "0.1uF/50V" WP_0603C 223.85,24.689 r90 bottom (schematic designator C230)
C231_UB1 "0.1uF/50V" WP_0603C 36.678,26.619 r270 bottom (schematic designator C231)
C231_UB2 "0.1uF/50V" WP_0603C 222.326,24.663 r90 bottom (schematic designator C231)
C232_UB1 "0.1uF/50V" WP_0603C 38.176,26.619 r270 bottom (schematic designator C232)
C232_UB2 "0.1uF/50V" WP_0603C 220.751,24.689 r90 bottom (schematic designator C232)
C233_UB1 "47uF/50V" WP_1210CC 72.212,17.221 r270 top (schematic designator C233)
C233_UB2 "47uF/50V" WP_1210CC 192.024,17.45 r270 top (schematic designator C233)
C234_UB1 "0.1uF/50V" WP_0603C 68.377,14.554 r90 bottom (schematic designator C234)
C234_UB2 "0.1uF/50V" WP_0603C 192.761,14.986 r90 bottom (schematic designator C234)
C235_UB1 "0.1uF/50V" WP_0603C 70.079,14.554 r90 bottom (schematic designator C235)
C235_UB2 "0.1uF/50V" WP_0603C 191.186,14.961 r90 bottom (schematic designator C235)
C236_UB1 "100pF/50V" WP_0603C 98.12,44.399 r180 top (schematic designator C236)
C236_UB2 "100pF/50V" WP_0603C 162.56,41.732 r180 top (schematic designator C236)
C237_UB1 "0.1uF/50V" WP_0603C 47.244,105.548 r180 bottom (schematic designator C237)
C237_UB2 "0.1uF/50V" WP_0603C 158.242,59.284 r0 bottom (schematic designator C237)
C238_UB1 "0.1uF/50V" WP_0603C 47.244,104.064 r180 bottom (schematic designator C238)
C238_UB2 "0.1uF/50V" WP_0603C 156.921,78.816 r0 bottom (schematic designator C238)
C241_UB1 "100pF/50V" WP_0603C 101.361,45.644 r0 top (schematic designator C241)
C241_UB2 "100pF/50V" WP_0603C 161.06,44.761 r0 top (schematic designator C241)
C242_UB1 "0.1uF/50V" WP_0603C 101.295,50.216 r0 top (schematic designator C242)
C242_UB2 "0.1uF/50V" WP_0603C 162.535,47.803 r180 top (schematic designator C242)
C248_UB1 "0.01uF/50V" WP_0603C 99.644,50.165 r90 top (schematic designator C248)
C248_UB2 "0.01uF/50V" WP_0603C 159.487,47.904 r90 top (schematic designator C248)
C250_UB1 "22uF/25V" WP_1206CC 100.305,36.22 r180 top (schematic designator C250)
C250_UB2 "22uF/25V" WP_1206CC 148.082,40.589 r0 top (schematic designator C250)
C251_UB1 "1nF/50V" WP_0603C 111.735,45.745 r0 top (schematic designator C251)
C251_UB2 "1nF/50V" WP_0603C 155.804,49.649 r0 top (schematic designator C251)
C252_UB1 "0.1uF/50V" WP_0603C 67.716,23.063 r0 top (schematic designator C252)
C252_UB2 "0.1uF/50V" WP_0603C 183.845,22.454 r0 top (schematic designator C252)
C254_UB1 "22uF/25V" WP_1206CC 71.272,40.64 r180 top (schematic designator C254)
C254_UB2 "22uF/25V" WP_1206CC 186.919,40.361 r180 top (schematic designator C254)
C255_UB1 "22uF/25V" WP_1206CC 71.222,43.18 r180 top (schematic designator C255)
C255_UB2 "22uF/25V" WP_1206CC 186.919,42.901 r180 top (schematic designator C255)
C256_UB1 "47uF/50V" WP_1210CC 55.428,120.218 r90 top (schematic designator C256)
C256_UB2 "47uF/50V" WP_1210CC 205.689,120.802 r90 top (schematic designator C256)
C257_UB1 "47uF/50V" WP_1210CC 61.341,120.218 r90 top (schematic designator C257)
C257_UB2 "47uF/50V" WP_1210CC 200.076,120.828 r90 top (schematic designator C257)
C258_UB1 "100pF/50V" WP_0603C 75.387,40.081 r0 top (schematic designator C258)
C258_UB2 "100pF/50V" WP_0603C 189.382,36.373 r0 top (schematic designator C258)
C259_UB1 "22uF/25V" WP_1206CC 113.011,52.553 r270 top (schematic designator C259)
C259_UB2 "22uF/25V" WP_1206CC 162.331,54.991 r90 bottom (schematic designator C259)
C260_UB1 "1uF/50V" WP_0603C 108.56,56.947 r90 bottom (schematic designator C260)
C260_UB2 "1uF/50V" WP_0603C 159.741,55.27 r90 bottom (schematic designator C260)
C261_UB1 "0.1uF/50V" WP_0603C 107.188,42.748 r90 top (schematic designator C261)
C261_UB2 "0.1uF/50V" WP_0603C 162.281,53.162 r270 bottom (schematic designator C261)
C262_UB1 "0.01uF/50V" WP_0603C 107.137,56.947 r90 bottom (schematic designator C262)
C262_UB2 "0.01uF/50V" WP_0603C 156.108,43.231 r0 bottom (schematic designator C262)
C263_UB1 "22uF/25V" WP_1206CC 75.311,17.145 r270 top (schematic designator C263)
C263_UB2 "22uF/25V" WP_1206CC 185.115,17.374 r270 top (schematic designator C263)
C264_UB1 "0.1uF/50V" WP_0603C 70.79,19.304 r90 top (schematic designator C264)
C264_UB2 "0.1uF/50V" WP_0603C 190.094,19.787 r180 top (schematic designator C264)
C265_UB1 "22uF/25V" WP_1206CC 108.128,63.906 r90 bottom (schematic designator C265)
C265_UB2 "22uF/25V" WP_1206CC 151.841,66.711 r180 top (schematic designator C265)
C266_UB1 "0.01uF/50V" WP_0603C 109.652,61.214 r180 bottom (schematic designator C266)
C266_UB2 "0.01uF/50V" WP_0603C 150.165,64.795 r0 top (schematic designator C266)
C267_UB1 "22uF/25V" WP_1206CC 110.388,52.578 r270 top (schematic designator C267)
C267_UB2 "22uF/25V" WP_1206CC 166.345,49.2 r270 top (schematic designator C267)
C268_UB1 "0.1uF/50V" WP_0603C 105.004,56.947 r90 bottom (schematic designator C268)
C268_UB2 "0.1uF/50V" WP_0603C 158.293,55.27 r90 bottom (schematic designator C268)
C269_UB1 "0.1uF/50V" WP_0603C 30.48,96.698 r0 bottom (schematic designator C269)
C269_UB2 "0.1uF/50V" WP_0603C 238.658,97.003 r0 bottom (schematic designator C269)
C270_UB1 "47uF/50V" WP_1210CC 23.927,87.782 r180 top (schematic designator C270)
C270_UB2 "47uF/50V" WP_1210CC 241.28,86.055 r180 top (schematic designator C270)
C271_UB1 "47uF/50V" WP_1210CC 23.927,83.998 r180 top (schematic designator C271)
C271_UB2 "47uF/50V" WP_1210CC 241.28,89.916 r180 top (schematic designator C271)
C272_UB1 "0.1uF/50V" WP_0603C 30.531,92.405 r0 bottom (schematic designator C272)
C272_UB2 "0.1uF/50V" WP_0603C 238.608,98.603 r0 bottom (schematic designator C272)
C273_UB1 "0.01uF/50V" WP_0603C 75.717,19.406 r90 top (schematic designator C273)
C273_UB2 "0.01uF/50V" WP_0603C 193.192,19.837 r90 top (schematic designator C273)
C274_UB1 "22pF/50V" WP_0603C 75.387,33.503 r270 top (schematic designator C274)
C274_UB2 "22pF/50V" WP_0603C 190.886,33.376 r270 top (schematic designator C274)
C275_UB1 "2.2nF/50V" WP_0603C 73.838,33.503 r270 top (schematic designator C275)
C275_UB2 "2.2nF/50V" WP_0603C 189.332,33.376 r270 top (schematic designator C275)
C276_UB1 "47uF/50V" WP_1210CC 23.927,70.18 r180 top (schematic designator C276)
C276_UB2 "47uF/50V" WP_1210CC 241.452,71.933 r180 top (schematic designator C276)
C277_UB1 "0.1uF/50V" WP_0603C 21.565,67.335 r0 top (schematic designator C277)
C277_UB2 "0.1uF/50V" WP_0603C 239.039,29.362 r90 top (schematic designator C277)
C278_UB1 "47uF/50V" WP_1210CC 38.044,123.622 r270 top (schematic designator C278)
C278_UB2 "47uF/50V" WP_1210CC 231.419,120.015 r90 top (schematic designator C278)
C279_UB1 "47uF/50V" WP_1210CC 34.31,123.622 r270 top (schematic designator C279)
C279_UB2 "47uF/50V" WP_1210CC 234.905,120.04 r90 top (schematic designator C279)
C280_UB1 "0.1uF/50V" WP_0603C 40.64,119.075 r270 bottom (schematic designator C280)
C280_UB2 "0.1uF/50V" WP_0603C 200.787,119.863 r180 bottom (schematic designator C280)
C281_UB1 "0.1uF/50V" WP_0603C 45.745,122.123 r270 top (schematic designator C281)
C281_UB2 "0.1uF/50V" WP_0603C 206.502,119.558 r180 bottom (schematic designator C281)
C282_UB1 "0.1uF/50V" WP_0603C 51.257,122.199 r270 top (schematic designator C282)
C282_UB2 "0.1uF/50V" WP_0603C 209.931,121.971 r270 bottom (schematic designator C282)
C283_UB1 "47uF/50V" WP_1210CC 26.893,123.647 r270 top (schematic designator C283)
C283_UB2 "47uF/50V" WP_1210CC 227.736,119.863 r90 top (schematic designator C283)
C284_UB1 "22uF/25V" WP_1206CC 104.013,54.331 r0 bottom (schematic designator C284)
C284_UB2 "22uF/25V" WP_1206CC 141.427,42.596 r270 bottom (schematic designator C284)
C285_UB1 "0.1uF/50V" WP_0603C 103.429,58.471 r270 bottom (schematic designator C285)
C285_UB2 "0.1uF/50V" WP_0603C 185.928,121.082 r270 bottom (schematic designator C285)
C286_UB1 "0.1uF/50V" WP_0603C 96.774,39.04 r270 bottom (schematic designator C286)
C286_UB2 "0.1uF/50V" WP_0603C 165.811,36.246 r270 top (schematic designator C286)
C287_UB1 "0.1uF/50V" WP_0603C 96.774,40.716 r90 bottom (schematic designator C287)
C287_UB2 "0.1uF/50V" WP_0603C 165.837,37.922 r90 top (schematic designator C287)
C288_UB1 "47uF/50V" WP_1210CC 109.017,35.865 r0 top (schematic designator C288)
C288_UB2 "47uF/50V" WP_1210CC 163.119,37.922 r270 top (schematic designator C288)
C289_UB1 "22uF/50V" WP_1206CC 98.831,38.71 r90 bottom (schematic designator C289)
C289_UB2 "22uF/50V" WP_1206CC 160.02,37.998 r270 top (schematic designator C289)
C290_UB1 "0.1uF/50V" WP_0603C 79.477,23.038 r0 top (schematic designator C290)
C290_UB2 "0.1uF/50V" WP_0603C 172.161,21.285 r0 top (schematic designator C290)
C291_UB1 "22uF/25V" WP_1206CC 82.448,40.767 r180 top (schematic designator C291)
C291_UB2 "22uF/25V" WP_1206CC 174.117,42.951 r180 top (schematic designator C291)
C292_UB1 "22uF/25V" WP_1206CC 82.525,43.282 r180 top (schematic designator C292)
C292_UB2 "22uF/25V" WP_1206CC 174.117,40.488 r180 top (schematic designator C292)
C293_UB1 "100pF/50V" WP_0603C 86.487,39.954 r0 top (schematic designator C293)
C293_UB2 "100pF/50V" WP_0603C 176.962,36.449 r0 top (schematic designator C293)
C294_UB1 "22uF/25V" WP_1206CC 82.017,17.475 r0 top (schematic designator C294)
C294_UB2 "22uF/25V" WP_1206CC 177.521,17.907 r0 top (schematic designator C294)
C295_UB1 "0.1uF/50V" WP_0603C 81.661,19.66 r90 top (schematic designator C295)
C295_UB2 "0.1uF/50V" WP_0603C 177.597,19.837 r180 top (schematic designator C295)
C296_UB1 "0.01uF/50V" WP_0603C 86.665,19.685 r90 top (schematic designator C296)
C296_UB2 "0.01uF/50V" WP_0603C 180.619,19.837 r90 top (schematic designator C296)
C297_UB1 "22pF/50V" WP_0603C 86.512,33.579 r270 top (schematic designator C297)
C297_UB2 "22pF/50V" WP_0603C 178.562,33.401 r270 top (schematic designator C297)
C298_UB1 "2.2nF/50V" WP_0603C 84.938,33.579 r270 top (schematic designator C298)
C298_UB2 "2.2nF/50V" WP_0603C 177.063,33.401 r270 top (schematic designator C298)
C299_UB1 "100pF/50V" WP_0603C 70.485,104.877 r0 top (schematic designator C299)
C299_UB2 "100pF/50V" WP_0603C 182.956,105.258 r0 top (schematic designator C299)
C300_UB1 "100pF/50V" WP_0603C 78.745,116.053 r180 top (schematic designator C300)
C300_UB2 "100pF/50V" WP_0603C 191.11,116.103 r180 top (schematic designator C300)
C301_UB1 "100pF/50V" WP_0603C 70.46,93.802 r0 top (schematic designator C301)
C301_UB2 "100pF/50V" WP_0603C 183.083,94.412 r0 top (schematic designator C301)
C302_UB1 "1nF/50V" WP_0603C 76.302,114.071 r180 top (schematic designator C302)
C302_UB2 "1nF/50V" WP_0603C 188.189,114.198 r180 top (schematic designator C302)
C303_UB1 "1nF/50V" WP_0603C 79.273,120.447 r90 top (schematic designator C303)
C303_UB2 "1nF/50V" WP_0603C 191.364,119.888 r90 top (schematic designator C303)
C304_UB1 "1nF/50V" WP_0603C 76.378,102.794 r180 top (schematic designator C304)
C304_UB2 "1nF/50V" WP_0603C 187.935,103.454 r180 top (schematic designator C304)
C305_UB1 "0.1uF/50V" WP_0603C 45.745,122.123 r270 bottom (schematic designator C305)
C305_UB2 "0.1uF/50V" WP_0603C 215.798,120.523 r90 top (schematic designator C305)
C306_UB1 "0.1uF/50V" WP_0603C 47.168,122.123 r270 bottom (schematic designator C306)
C306_UB2 "0.1uF/50V" WP_0603C 220.777,117.729 r90 bottom (schematic designator C306)
C307_UB1 "0.1uF/50V" WP_0603C 51.257,122.225 r270 bottom (schematic designator C307)
C307_UB2 "0.1uF/50V" WP_0603C 209.931,121.971 r270 top (schematic designator C307)
C308_UB1 "0.1uF/50V" WP_0603C 49.682,122.225 r270 bottom (schematic designator C308)
C308_UB2 "0.1uF/50V" WP_0603C 211.43,121.945 r270 top (schematic designator C308)
C309_UB1 "22uF/25V" WP_1206CC 92.481,61.798 r180 top (schematic designator C309)
C309_UB2 "22uF/25V" WP_1206CC 174.549,86.233 r180 top (schematic designator C309)
C310_UB1 "33pF/50V" WP_0603C 110.566,64.313 r0 bottom (schematic designator C310)
C310_UB2 "33pF/50V" WP_0603C 165.075,61.138 r0 bottom (schematic designator C310)
C311_UB1 "22uF/25V" WP_1206CC 74.651,119.482 r90 bottom (schematic designator C311)
C311_UB2 "22uF/25V" WP_1206CC 186.741,98.349 r90 bottom (schematic designator C311)
C312_UB1 "22uF/25V" WP_1206CC 68.605,97.333 r90 top (schematic designator C312)
C312_UB2 "22uF/25V" WP_1206CC 156.312,55.931 r90 bottom (schematic designator C312)
C313_UB1 "22uF/25V" WP_1206CC 56.21,43.815 r270 top (schematic designator C313)
C313_UB2 "22uF/25V" WP_1206CC 202.692,43.637 r270 top (schematic designator C313)
C314_UB1 "22uF/25V" WP_1206CC 65.456,43.205 r270 top (schematic designator C314)
C314_UB2 "22uF/25V" WP_1206CC 212.293,43.663 r270 top (schematic designator C314)
C315_UB1 "22uF/25V" WP_1206CC 104.927,63.652 r180 bottom (schematic designator C315)
C315_UB2 "22uF/25V" WP_1206CC 159.233,64.389 r180 bottom (schematic designator C315)
C316_UB1 "0.1uF/50V" WP_0603C 78.664,69.164 r270 bottom (schematic designator C316)
C316_UB2 "0.1uF/50V" WP_0603C 179.375,96.977 r90 bottom (schematic designator C316)
C317_UB1 "0.1uF/50V" WP_0603C 84.887,43.129 r0 top (schematic designator C317)
C317_UB2 "0.1uF/50V" WP_0603C 158.394,62.459 r180 bottom (schematic designator C317)
C318_UB1 "0.1uF/50V" WP_0603C 99.263,85.954 r0 top (schematic designator C318)
C318_UB2 "0.1uF/50V" WP_0603C 174.269,83.82 r180 top (schematic designator C318)
C319_UB1 "100pF/50V" WP_0603C 78.842,104.877 r180 top (schematic designator C319)
C319_UB2 "100pF/50V" WP_0603C 191.084,105.258 r180 top (schematic designator C319)
C320_UB1 "0.1uF/50V" WP_0603C 56.718,46.228 r180 top (schematic designator C320)
C320_UB2 "0.1uF/50V" WP_0603C 200.685,43.713 r270 top (schematic designator C320)
C321_UB1 "0.1uF/50V" WP_0603C 66.192,45.263 r0 top (schematic designator C321)
C321_UB2 "0.1uF/50V" WP_0603C 214.782,43.815 r0 top (schematic designator C321)
C322_UB1 "33pF/50V" WP_0603C 110.566,62.713 r0 bottom (schematic designator C322)
C322_UB2 "33pF/50V" WP_0603C 165.075,59.702 r0 bottom (schematic designator C322)
C323_UB1 "0.1uF/50V" WP_0603C 108.255,86.385 r0 bottom (schematic designator C323)
C323_UB2 "0.1uF/50V" WP_0603C 184.252,50.952 r90 bottom (schematic designator C323)
C324_UB1 "100pF/50V" WP_0603C 70.688,116.053 r0 top (schematic designator C324)
C324_UB2 "100pF/50V" WP_0603C 183.134,116.129 r0 top (schematic designator C324)
C325_UB1 "100pF/50V" WP_0603C 78.765,93.701 r180 top (schematic designator C325)
C325_UB2 "100pF/50V" WP_0603C 191.16,94.336 r180 top (schematic designator C325)
C326_UB1 "1nF/50V" WP_0603C 79.197,109.271 r90 top (schematic designator C326)
C326_UB2 "1nF/50V" WP_0603C 191.491,109.093 r90 top (schematic designator C326)
C327_UB1 "0.1uF/50V" WP_0603C 75.783,108.382 r90 bottom (schematic designator C327)
C327_UB2 "0.1uF/50V" WP_0603C 139.471,40.73 r270 bottom (schematic designator C327)
C328_UB1 "0.1uF/50V" WP_0603C 74.27,108.382 r90 bottom (schematic designator C328)
C328_UB2 "0.1uF/50V" WP_0603C 154.381,57.836 r90 bottom (schematic designator C328)
C329_UB1 "1nF/50V" WP_0603C 75.342,124.917 r180 top (schematic designator C329)
C329_UB2 "1nF/50V" WP_0603C 188.011,125.019 r180 top (schematic designator C329)
C330_UB1 "1nF/50V" WP_0603C 79.223,97.993 r90 top (schematic designator C330)
C330_UB2 "1nF/50V" WP_0603C 191.592,97.917 r90 top (schematic designator C330)
C331_UB1 "0.1uF/50V" WP_0603C 50.267,40.691 r90 top (schematic designator C331)
C331_UB2 "0.1uF/50V" WP_0603C 217.78,81.509 r270 bottom (schematic designator C331)
C332_UB1 "0.1uF/50V" WP_0603C 59.792,53.746 r90 bottom (schematic designator C332)
C332_UB2 "0.1uF/50V" WP_0603C 211.785,81.737 r270 bottom (schematic designator C332)
C333_UB1 "0.1uF/50V" WP_0603C 65.507,66.65 r180 bottom (schematic designator C333)
C333_UB2 "0.1uF/50V" WP_0603C 222.326,65.278 r180 bottom (schematic designator C333)
C334_UB1 "0.1uF/50V" WP_0603C 65.354,73.609 r180 bottom (schematic designator C334)
C334_UB2 "0.1uF/50V" WP_0603C 194.818,71.044 r0 bottom (schematic designator C334)
C335_UB1 "0.1uF/50V" WP_0603C 54.737,53.772 r90 bottom (schematic designator C335)
C335_UB2 "0.1uF/50V" WP_0603C 206.375,81.661 r270 bottom (schematic designator C335)
C336_UB1 "0.1uF/50V" WP_0603C 37.973,70.104 r0 bottom (schematic designator C336)
C336_UB2 "0.1uF/50V" WP_0603C 193.751,75.54 r0 bottom (schematic designator C336)
C337_UB1 "0.1uF/50V" WP_0603C 65.634,58.903 r180 bottom (schematic designator C337)
C337_UB2 "0.1uF/50V" WP_0603C 203.378,54.051 r90 bottom (schematic designator C337)
C338_UB1 "0.1uF/50V" WP_0603C 47.346,53.746 r90 bottom (schematic designator C338)
C338_UB2 "0.1uF/50V" WP_0603C 207.239,53.772 r90 bottom (schematic designator C338)
C339_UB1 "0.1uF/50V" WP_0603C 52.248,74.092 r90 bottom (schematic designator C339)
C339_UB2 "0.1uF/50V" WP_0603C 211.531,53.975 r90 bottom (schematic designator C339)
C340_UB1 "0.1uF/50V" WP_0603C 51.613,81.128 r270 bottom (schematic designator C340)
C340_UB2 "0.1uF/50V" WP_0603C 216.56,54.102 r90 bottom (schematic designator C340)
C341_UB1 "0.1uF/50V" WP_0603C 55.093,81.153 r270 bottom (schematic designator C341)
C341_UB2 "0.1uF/50V" WP_0603C 222.326,63.5 r180 bottom (schematic designator C341)
C342_UB1 "0.1uF/50V" WP_0603C 60.731,81.153 r270 bottom (schematic designator C342)
C342_UB2 "0.1uF/50V" WP_0603C 222.631,74.193 r180 bottom (schematic designator C342)
C343_UB1 "0.1uF/50V" WP_0603C 36.957,80.213 r90 bottom (schematic designator C343)
C343_UB2 "0.1uF/50V" WP_0603C 193.954,82.169 r180 top (schematic designator C343)
C344_UB1 "0.1uF/50V" WP_0603C 47.219,80.899 r270 bottom (schematic designator C344)
C344_UB2 "0.1uF/50V" WP_0603C 195.428,80.747 r270 bottom (schematic designator C344)
C345_UB1 "0.1uF/50V" WP_0603C 48.666,80.899 r270 bottom (schematic designator C345)
C345_UB2 "0.1uF/50V" WP_0603C 193.954,80.696 r270 bottom (schematic designator C345)
C346_UB1 "0.1uF/50V" WP_0603C 58.496,59.665 r90 bottom (schematic designator C346)
C346_UB2 "0.1uF/50V" WP_0603C 222.631,77.14 r180 bottom (schematic designator C346)
C347_UB1 "0.1uF/50V" WP_0603C 49.886,53.797 r90 bottom (schematic designator C347)
C347_UB2 "0.1uF/50V" WP_0603C 201.447,54 r90 bottom (schematic designator C347)
C348_UB1 "0.1uF/50V" WP_0603C 43.078,53.772 r90 bottom (schematic designator C348)
C348_UB2 "0.1uF/50V" WP_0603C 222.656,75.667 r180 bottom (schematic designator C348)
C349_UB1 "0.1uF/50V" WP_0603C 38.075,65.557 r0 bottom (schematic designator C349)
C349_UB2 "0.1uF/50V" WP_0603C 222.377,69.926 r180 bottom (schematic designator C349)
C350_UB1 "0.1uF/50V" WP_0603C 65.532,61.239 r180 bottom (schematic designator C350)
C350_UB2 "0.1uF/50V" WP_0603C 213.843,54 r90 bottom (schematic designator C350)
C351_UB1 "0.1uF/50V" WP_0603C 65.507,69.596 r180 bottom (schematic designator C351)
C351_UB2 "0.1uF/50V" WP_0603C 199.949,54 r90 bottom (schematic designator C351)
C352_UB1 "0.1uF/50V" WP_0603C 65.303,75.311 r180 bottom (schematic designator C352)
C352_UB2 "0.1uF/50V" WP_0603C 194.894,65.303 r0 bottom (schematic designator C352)
C353_UB1 "0.1uF/50V" WP_0603C 58.166,81.001 r270 bottom (schematic designator C353)
C353_UB2 "0.1uF/50V" WP_0603C 194.894,63.881 r0 bottom (schematic designator C353)
C354_UB1 "1nF/50V" WP_0603C 42.621,80.924 r270 bottom (schematic designator C354)
C354_UB2 "1nF/50V" WP_0603C 201.473,75.971 r90 bottom (schematic designator C354)
C355_UB1 "1nF/50V" WP_0603C 40.742,74.27 r90 bottom (schematic designator C355)
C355_UB2 "1nF/50V" WP_0603C 197.561,75.946 r90 bottom (schematic designator C355)
C356_UB1 "22uF/25V" WP_1206CC 64.211,63.627 r0 bottom (schematic designator C356)
C356_UB2 "22uF/25V" WP_1206CC 213.817,80.213 r90 bottom (schematic designator C356)
C357_UB1 "22uF/25V" WP_1206CC 45.314,55.321 r90 bottom (schematic designator C357)
C357_UB2 "22uF/25V" WP_1206CC 221.158,67.234 r0 bottom (schematic designator C357)
C358_UB1 "22uF/25V" WP_1206CC 50.241,75.438 r270 bottom (schematic designator C358)
C358_UB2 "22uF/25V" WP_1206CC 205.257,55.169 r270 bottom (schematic designator C358)
C359_UB1 "22uF/25V" WP_1206CC 52.349,44.12 r270 top (schematic designator C359)
C359_UB2 "22uF/25V" WP_1206CC 195.326,73.613 r180 bottom (schematic designator C359)
C360_UB1 "1nF/50V" WP_0603C 43.713,74.295 r90 bottom (schematic designator C360)
C360_UB2 "1nF/50V" WP_0603C 202.641,73.304 r90 bottom (schematic designator C360)
C361_UB1 "1nF/50V" WP_0603C 41.072,80.874 r270 bottom (schematic designator C361)
C361_UB2 "1nF/50V" WP_0603C 198.984,75.971 r90 bottom (schematic designator C361)
C362_UB1 "22uF/25V" WP_1206CC 114.529,72.796 r0 top (schematic designator C362)
C362_UB2 "22uF/25V" WP_1206CC 163.271,71.018 r0 top (schematic designator C362)
C363_UB1 "1uF/50V" WP_0603C 111.557,78.969 r90 bottom (schematic designator C363)
C363_UB2 "1uF/50V" WP_0603C 159.563,74.854 r270 bottom (schematic designator C363)
C364_UB1 "0.1uF/50V" WP_0603C 113.03,78.969 r90 bottom (schematic designator C364)
C364_UB2 "0.1uF/50V" WP_0603C 161.036,74.854 r270 bottom (schematic designator C364)
C365_UB1 "0.01uF/50V" WP_0603C 125.095,48.057 r90 bottom (schematic designator C365)
C365_UB2 "0.01uF/50V" WP_0603C 162.509,74.854 r270 bottom (schematic designator C365)
C366_UB1 "0.01uF/50V" WP_0603C 25.502,57.76 r0 bottom (schematic designator C366)
C366_UB2 "0.01uF/50V" WP_0603C 235.616,58.268 r180 bottom (schematic designator C366)
C367_UB1 "22uF/25V" WP_1206CC 108.864,82.906 r180 bottom (schematic designator C367)
C367_UB2 "22uF/25V" WP_1206CC 161.544,64.237 r0 bottom (schematic designator C367)
C368_UB1 "0.01uF/50V" WP_0603C 114.173,83.439 r270 bottom (schematic designator C368)
C368_UB2 "0.01uF/50V" WP_0603C 213.081,94.336 r0 bottom (schematic designator C368)
C369_UB1 "22uF/25V" WP_1206CC 112.293,72.822 r180 top (schematic designator C369)
C369_UB2 "22uF/25V" WP_1206CC 157.683,71.018 r0 top (schematic designator C369)
C370_UB1 "0.1uF/50V" WP_0603C 110.134,78.969 r90 bottom (schematic designator C370)
C370_UB2 "0.1uF/50V" WP_0603C 158.471,77.394 r180 bottom (schematic designator C370)
C371_UB1 "1nF/50V" WP_0603C 44.145,80.924 r270 bottom (schematic designator C371)
C371_UB2 "1nF/50V" WP_0603C 203.835,75.946 r90 bottom (schematic designator C371)
C372_UB1 "1nF/50V" WP_0603C 42.24,74.27 r90 bottom (schematic designator C372)
C372_UB2 "1nF/50V" WP_0603C 200.203,73.355 r90 bottom (schematic designator C372)
C373_UB1 "22uF/25V" WP_1206CC 106.629,72.796 r180 top (schematic designator C373)
C373_UB2 "22uF/25V" WP_1206CC 155.397,70.993 r180 top (schematic designator C373)
C374_UB1 "0.1uF/50V" WP_0603C 108.382,80.518 r270 bottom (schematic designator C374)
C374_UB2 "0.1uF/50V" WP_0603C 185.903,110.338 r270 bottom (schematic designator C374)
C375_UB1 "0.01uF/50V" WP_0603C 27.051,46.634 r180 bottom (schematic designator C375)
C375_UB2 "0.01uF/50V" WP_0603C 233.985,46.584 r0 bottom (schematic designator C375)
C376_UB1 "0.01uF/50V" WP_0603C 27.051,51.232 r180 bottom (schematic designator C376)
C376_UB2 "0.01uF/50V" WP_0603C 233.985,51.41 r0 bottom (schematic designator C376)
C377_UB1 "0.1uF/50V" WP_0603C 98.984,36.805 r270 bottom (schematic designator C377)
C377_UB2 "0.1uF/50V" WP_0603C 147.244,46.076 r90 top (schematic designator C377)
C378_UB1 "0.1uF/50V" WP_0603C 100.508,36.805 r270 bottom (schematic designator C378)
C378_UB2 "0.1uF/50V" WP_0603C 147.244,44.552 r270 top (schematic designator C378)
C379_UB1 "47uF/50V" WP_1210CC 97.053,46.482 r90 top (schematic designator C379)
C379_UB2 "47uF/50V" WP_1210CC 149.784,43.612 r90 top (schematic designator C379)
C380_UB1 "0.1uF/50V" WP_0603C 34.417,74.117 r180 bottom (schematic designator C380)
C380_UB2 "0.1uF/50V" WP_0603C 190.322,69.926 r180 top (schematic designator C380)
C381_UB1 "22uF/25V" WP_1206CC 33.409,73.66 r180 top (schematic designator C381)
C381_UB2 "22uF/25V" WP_1206CC 192.049,71.857 r180 top (schematic designator C381)
C382_UB1 "22uF/25V" WP_1206CC 33.409,76.2 r180 top (schematic designator C382)
C382_UB2 "22uF/25V" WP_1206CC 192.075,74.32 r180 top (schematic designator C382)
C383_UB1 "22uF/25V" WP_1206CC 87.147,79.087 r180 top (schematic designator C383)
C383_UB2 "22uF/25V" WP_1206CC 176.403,61.951 r180 top (schematic designator C383)
C384_UB1 "33pF/50V" WP_0603C 115.595,84.898 r0 bottom (schematic designator C384)
C384_UB2 "33pF/50V" WP_0603C 164.567,82.575 r0 bottom (schematic designator C384)
C385_UB1 "22uF/25V" WP_1206CC 95.225,75.743 r270 top (schematic designator C385)
C385_UB2 "22uF/25V" WP_1206CC 158.471,86.385 r180 bottom (schematic designator C385)
C386_UB1 "0.1uF/50V" WP_0603C 85.954,89.916 r270 bottom (schematic designator C386)
C386_UB2 "0.1uF/50V" WP_0603C 181.813,52.578 r270 bottom (schematic designator C386)
C387_UB1 "0.1uF/50V" WP_0603C 77.165,77.673 r270 bottom (schematic designator C387)
C387_UB2 "0.1uF/50V" WP_0603C 172.314,91.389 r90 bottom (schematic designator C387)
C388_UB1 "0.1uF/50V" WP_0603C 82.652,60.757 r180 bottom (schematic designator C388)
C388_UB2 "0.1uF/50V" WP_0603C 179.934,73.533 r90 bottom (schematic designator C388)
C389_UB1 "0.1uF/50V" WP_0603C 34.341,75.565 r180 bottom (schematic designator C389)
C389_UB2 "0.1uF/50V" WP_0603C 190.348,76.251 r180 top (schematic designator C389)
C390_UB1 "33pF/50V" WP_0603C 115.621,83.424 r0 bottom (schematic designator C390)
C390_UB2 "33pF/50V" WP_0603C 164.592,80.975 r0 bottom (schematic designator C390)
C391_UB1 "0.1uF/50V" WP_0603C 108.255,84.938 r0 bottom (schematic designator C391)
C391_UB2 "0.1uF/50V" WP_0603C 156.032,84.353 r0 bottom (schematic designator C391)
C392_UB1 "0.1uF/50V" WP_0603C 34.341,77.114 r180 bottom (schematic designator C392)
C392_UB2 "0.1uF/50V" WP_0603C 190.348,77.648 r180 top (schematic designator C392)
C393_UB1 "22uF/25V" WP_1206CC 117.978,67.843 r0 top (schematic designator C393)
C393_UB2 "22uF/25V" WP_1206CC 142.559,65.862 r180 top (schematic designator C393)
C394_UB1 "22uF/25V" WP_1206CC 120.518,58.293 r180 top (schematic designator C394)
C394_UB2 "22uF/25V" WP_1206CC 140.843,56.54 r0 top (schematic designator C394)
C395_UB1 "0.1uF/50V" WP_0603C 115.895,68.758 r270 top (schematic designator C395)
C395_UB2 "0.1uF/50V" WP_0603C 144.729,65.151 r90 top (schematic designator C395)
C396_UB1 "0.1uF/50V" WP_0603C 118.663,56.134 r180 top (schematic designator C396)
C396_UB2 "0.1uF/50V" WP_0603C 138.938,56.21 r90 top (schematic designator C396)
C397_UB1 "0.1uF/50V" WP_0603C 119.355,52.68 r0 top (schematic designator C397)
C397_UB2 "0.1uF/50V" WP_0603C 141.732,52.781 r180 top (schematic designator C397)
C398_UB1 "22uF/25V" WP_1206CC 44.78,69.037 r90 bottom (schematic designator C402)
C398_UB2 "22uF/25V" WP_1206CC 199.187,71.349 r0 bottom (schematic designator C402)
C399_UB1 "1uF/50V" WP_0603C 39.141,72.288 r90 bottom (schematic designator C399)
C399_UB2 "1uF/50V" WP_0603C 204.8,80.543 r180 bottom (schematic designator C399)
C400_UB1 "0.1uF/50V" WP_0603C 46.761,75.87 r270 bottom (schematic designator C400)
C400_UB2 "0.1uF/50V" WP_0603C 201.955,69.317 r0 bottom (schematic designator C400)
C401_UB1 "0.1uF/50V" WP_0603C 39.98,62.332 r0 bottom (schematic designator C401)
C401_UB2 "0.1uF/50V" WP_0603C 196.444,62.433 r180 bottom (schematic designator C401)
C402_UB1 "22uF/25V" WP_1206CC 39.37,60.249 r0 bottom (schematic designator C402)
C402_UB2 "22uF/25V" WP_1206CC 197.663,58.75 r180 bottom (schematic designator C402)
C403_UB1 "22pF/50V" WP_0603C 45.999,47.777 r0 bottom (schematic designator C403)
C403_UB2 "22pF/50V" WP_0603C 210.49,47.955 r0 bottom (schematic designator C403)
C404_UB1 "22pF/50V" WP_0603C 51.029,47.828 r180 bottom (schematic designator C404)
C404_UB2 "22pF/50V" WP_0603C 215.189,47.93 r180 bottom (schematic designator C404)
C405_UB1 "0.1uF/50V" WP_0603C 63.043,91.364 r90 top (schematic designator C405)
C405_UB2 "0.1uF/50V" WP_0603C 161.239,78.162 r90 bottom (schematic designator C405)
C406_UB1 "0.1uF/50V" WP_0603C 64.821,88.214 r90 top (schematic designator C406)
C406_UB2 "0.1uF/50V" WP_0603C 215.777,79.959 r90 bottom (schematic designator C406)
C407_UB1 "1uF/25V" WP_0603C 28.753,70.612 r270 top (schematic designator C407)
C407_UB2 "1uF/25V" WP_0603C 232.461,69.393 r90 top (schematic designator C407)
C408_UB1 "0.1uF/50V" WP_0603C 38.1,67.031 r0 bottom (schematic designator C408)
C408_UB2 "0.1uF/50V" WP_0603C 201.574,49.428 r90 bottom (schematic designator C408)
C409_UB1 "1uF/25V" WP_0603C 27.305,65.888 r90 top (schematic designator C409)
C409_UB2 "1uF/25V" WP_0603C 233.979,74.32 r270 top (schematic designator C409)
C410_UB1 "0.01uF/50V" WP_0603C 107.589,17.45 r0 bottom (schematic designator C410)
C410_UB2 "0.01uF/50V" WP_0603C 147.015,19.101 r270 bottom (schematic designator C410)
C411_UB1 "22uF/25V" WP_1206CC 108.636,19.304 r90 bottom (schematic designator C411)
C411_UB2 "22uF/25V" WP_1206CC 148.92,21.311 r270 bottom (schematic designator C411)
C412_UB1 "0.1uF/50V" WP_0603C 107.564,16.027 r0 bottom (schematic designator C412)
C412_UB2 "0.1uF/50V" WP_0603C 145.567,19.101 r270 bottom (schematic designator C412)
C413_UB1 "22uF/25V" WP_1206CC 91.542,30.124 r270 top (schematic designator C413)
C413_UB2 "22uF/25V" WP_1206CC 164.809,27.076 r90 bottom (schematic designator C413)
C414_UB1 "0.1uF/50V" WP_0603C 92.685,25.578 r180 bottom (schematic designator C414)
C414_UB2 "0.1uF/50V" WP_0603C 165.774,18.44 r180 top (schematic designator C414)
C415_UB1 "22uF/25V" WP_1206CC 92.126,27.788 r90 bottom (schematic designator C415)
C415_UB2 "22uF/25V" WP_1206CC 164.733,21.768 r270 bottom (schematic designator C415)
C416_UB1 "0.1uF/50V" WP_0603C 71.044,45.237 r180 top (schematic designator C416)
C416_UB2 "0.1uF/50V" WP_0603C 166.663,20.117 r270 bottom (schematic designator C416)
C417_UB1 "22uF/25V" WP_1206CC 92.024,21.361 r270 top (schematic designator C417)
C417_UB2 "22uF/25V" WP_1206CC 164.835,27.076 r90 top (schematic designator C417)
C418_UB1 "0.01uF/50V" WP_0603C 95.631,15.646 r180 top (schematic designator C418)
C418_UB2 "0.01uF/50V" WP_0603C 164.207,20.041 r90 top (schematic designator C418)
C419_UB1 "0.1uF/50V" WP_0603C 95.606,17.094 r180 top (schematic designator C419)
C419_UB2 "0.1uF/50V" WP_0603C 165.673,20.041 r90 top (schematic designator C419)
C420_UB1 "22uF/25V" WP_1206CC 111.15,20.853 r270 top (schematic designator C420)
C420_UB2 "22uF/25V" WP_1206CC 144.729,26.975 r90 top (schematic designator C420)
C421_UB1 "0.01uF/50V" WP_0603C 109.118,17.221 r180 top (schematic designator C421)
C421_UB2 "0.01uF/50V" WP_0603C 146.914,27.936 r0 top (schematic designator C421)
C422_UB1 "0.1uF/50V" WP_0603C 109.093,18.694 r180 top (schematic designator C422)
C422_UB2 "0.1uF/50V" WP_0603C 146.914,26.492 r0 top (schematic designator C422)
C424 "47uF/50V" WP_1210CC 135.433,61.011 r90 top
C425 "0.1uF/50V" WP_0603C 128.93,63.246 r0 bottom
C426 "0.1uF/50V" WP_0603C 128.93,61.798 r0 bottom
C427 "0.1uF/50V" WP_0603C 121.234,97.587 r90 top
C428 "47uF/50V" WP_1210CC 148.539,124.612 r0 top
C429 "47uF/50V" WP_1210CC 112.725,101.905 r180 top
C430 "0.1uF/50V" WP_0603C 111.851,104.445 r0 top
C431 "0.1uF/50V" WP_0603C 146.304,125.679 r270 top
C432 "22uF/25V" WP_1206CC 112.725,106.401 r180 top
C433 "22uF/25V" WP_1206CC 122.987,102.006 r90 top
C434 "0.1uF/50V" WP_0603C 110.312,104.445 r180 top
C435 "0.1uF/50V" WP_0603C 125.146,102.26 r90 top
C436 "22uF/25V" WP_1206CC 140.03,126.67 r90 top
C437 "22uF/25V" WP_1206CC 130.759,131.242 r270 top
C438 "0.1uF/50V" WP_0603C 141.961,126.644 r90 top
C439 "0.1uF/50V" WP_0603C 128.676,130.759 r270 top
C440 "22uF/25V" WP_1206CC 132.207,51.994 r90 top
C441 "0.01uF/50V" WP_0603C 132.588,72.263 r90 top
C442 "100pF/50V" WP_0603C 130.556,57.424 r180 top
C443 "100pF/50V" WP_0603C 129.083,67.691 r0 top
C444 "0.1uF/50V" WP_0603C 129.535,73.723 r0 top
C445 "0.01uF/50V" WP_0603C 126.467,73.685 r0 top
C446 "22uF/25V" WP_1206CC 127.432,52.095 r90 top
C447 "1nF/50V" WP_0603C 133.121,34.849 r90 top
C448 "1nF/50V" WP_0603C 133.101,48.172 r90 top
C449 "22uF/25V" WP_1206CC 132.207,104.064 r180 top
C450 "0.1uF/50V" WP_0603C 130.226,106.07 r180 top
C451 "0.1uF/50V" WP_0603C 129.819,120.142 r0 bottom
C452 "22uF/25V" WP_1206CC 127.584,125.273 r0 top
C453 "0.1uF/50V" WP_0603C 131.75,114.427 r90 bottom
C454 "0.1uF/50V" WP_0603C 129.591,111.227 r180 bottom
D13_UB1 "MBRS340T3" WP_SMC_DO214AB 20.955,34.315 r90 top (schematic designator D13)
D13_UB2 "MBRS340T3" WP_SMC_DO214AB 240.005,33.503 r90 top (schematic designator D13)
D16_UB1 "1N5819" WP_SOD-323 44.069,120.167 r90 top (schematic designator D16)
D16_UB2 "1N5819" WP_SOD-323 212.471,120.447 r90 bottom (schematic designator D16)
D20_UB1 "1N5822" WP_SMA_DO214AC 68.25,25.298 r90 top (schematic designator D20)
D20_UB2 "1N5822" WP_SMA_DO214AC 184.379,24.689 r90 top (schematic designator D20)
D21_UB1 "LED" WP_0603_LED 74.676,41.605 r90 top (schematic designator D21)
D21_UB2 "LED" WP_0603_LED 190.932,39.548 r0 top (schematic designator D21)
D22_UB1 "1N5822" WP_SMA_DO214AC 79.502,25.248 r90 top (schematic designator D22)
D22_UB2 "1N5822" WP_SMA_DO214AC 171.628,24.816 r90 top (schematic designator D22)
D23_UB1 "LED" WP_0603_LED 84.912,44.577 r90 top (schematic designator D23)
D23_UB2 "LED" WP_0603_LED 178.562,39.649 r0 top (schematic designator D23)
D24_UB1 "1N5819" WP_SOD-323 30.251,71.476 r0 top (schematic designator D24)
D24_UB2 "1N5819" WP_SOD-323 231.115,68.428 r180 top (schematic designator D24)
D25 "1N5822" WP_SMA_DO214AC 106.07,94.869 r0 top
D26 "1N5822" WP_SMA_DO214AC 155.931,131.572 r180 top
D27 "1N5822" WP_SMA_DO214AC 106.07,98.273 r0 top
D28 "1N5822" WP_SMA_DO214AC 155.931,128.168 r180 top
DR2_UB1 "SMCJ30CA-TR" WP_SMC_DO214AB 25.603,37.084 r0 top (schematic designator DR2)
